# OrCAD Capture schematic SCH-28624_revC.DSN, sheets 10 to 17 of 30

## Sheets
10 08 EC&SD: size B
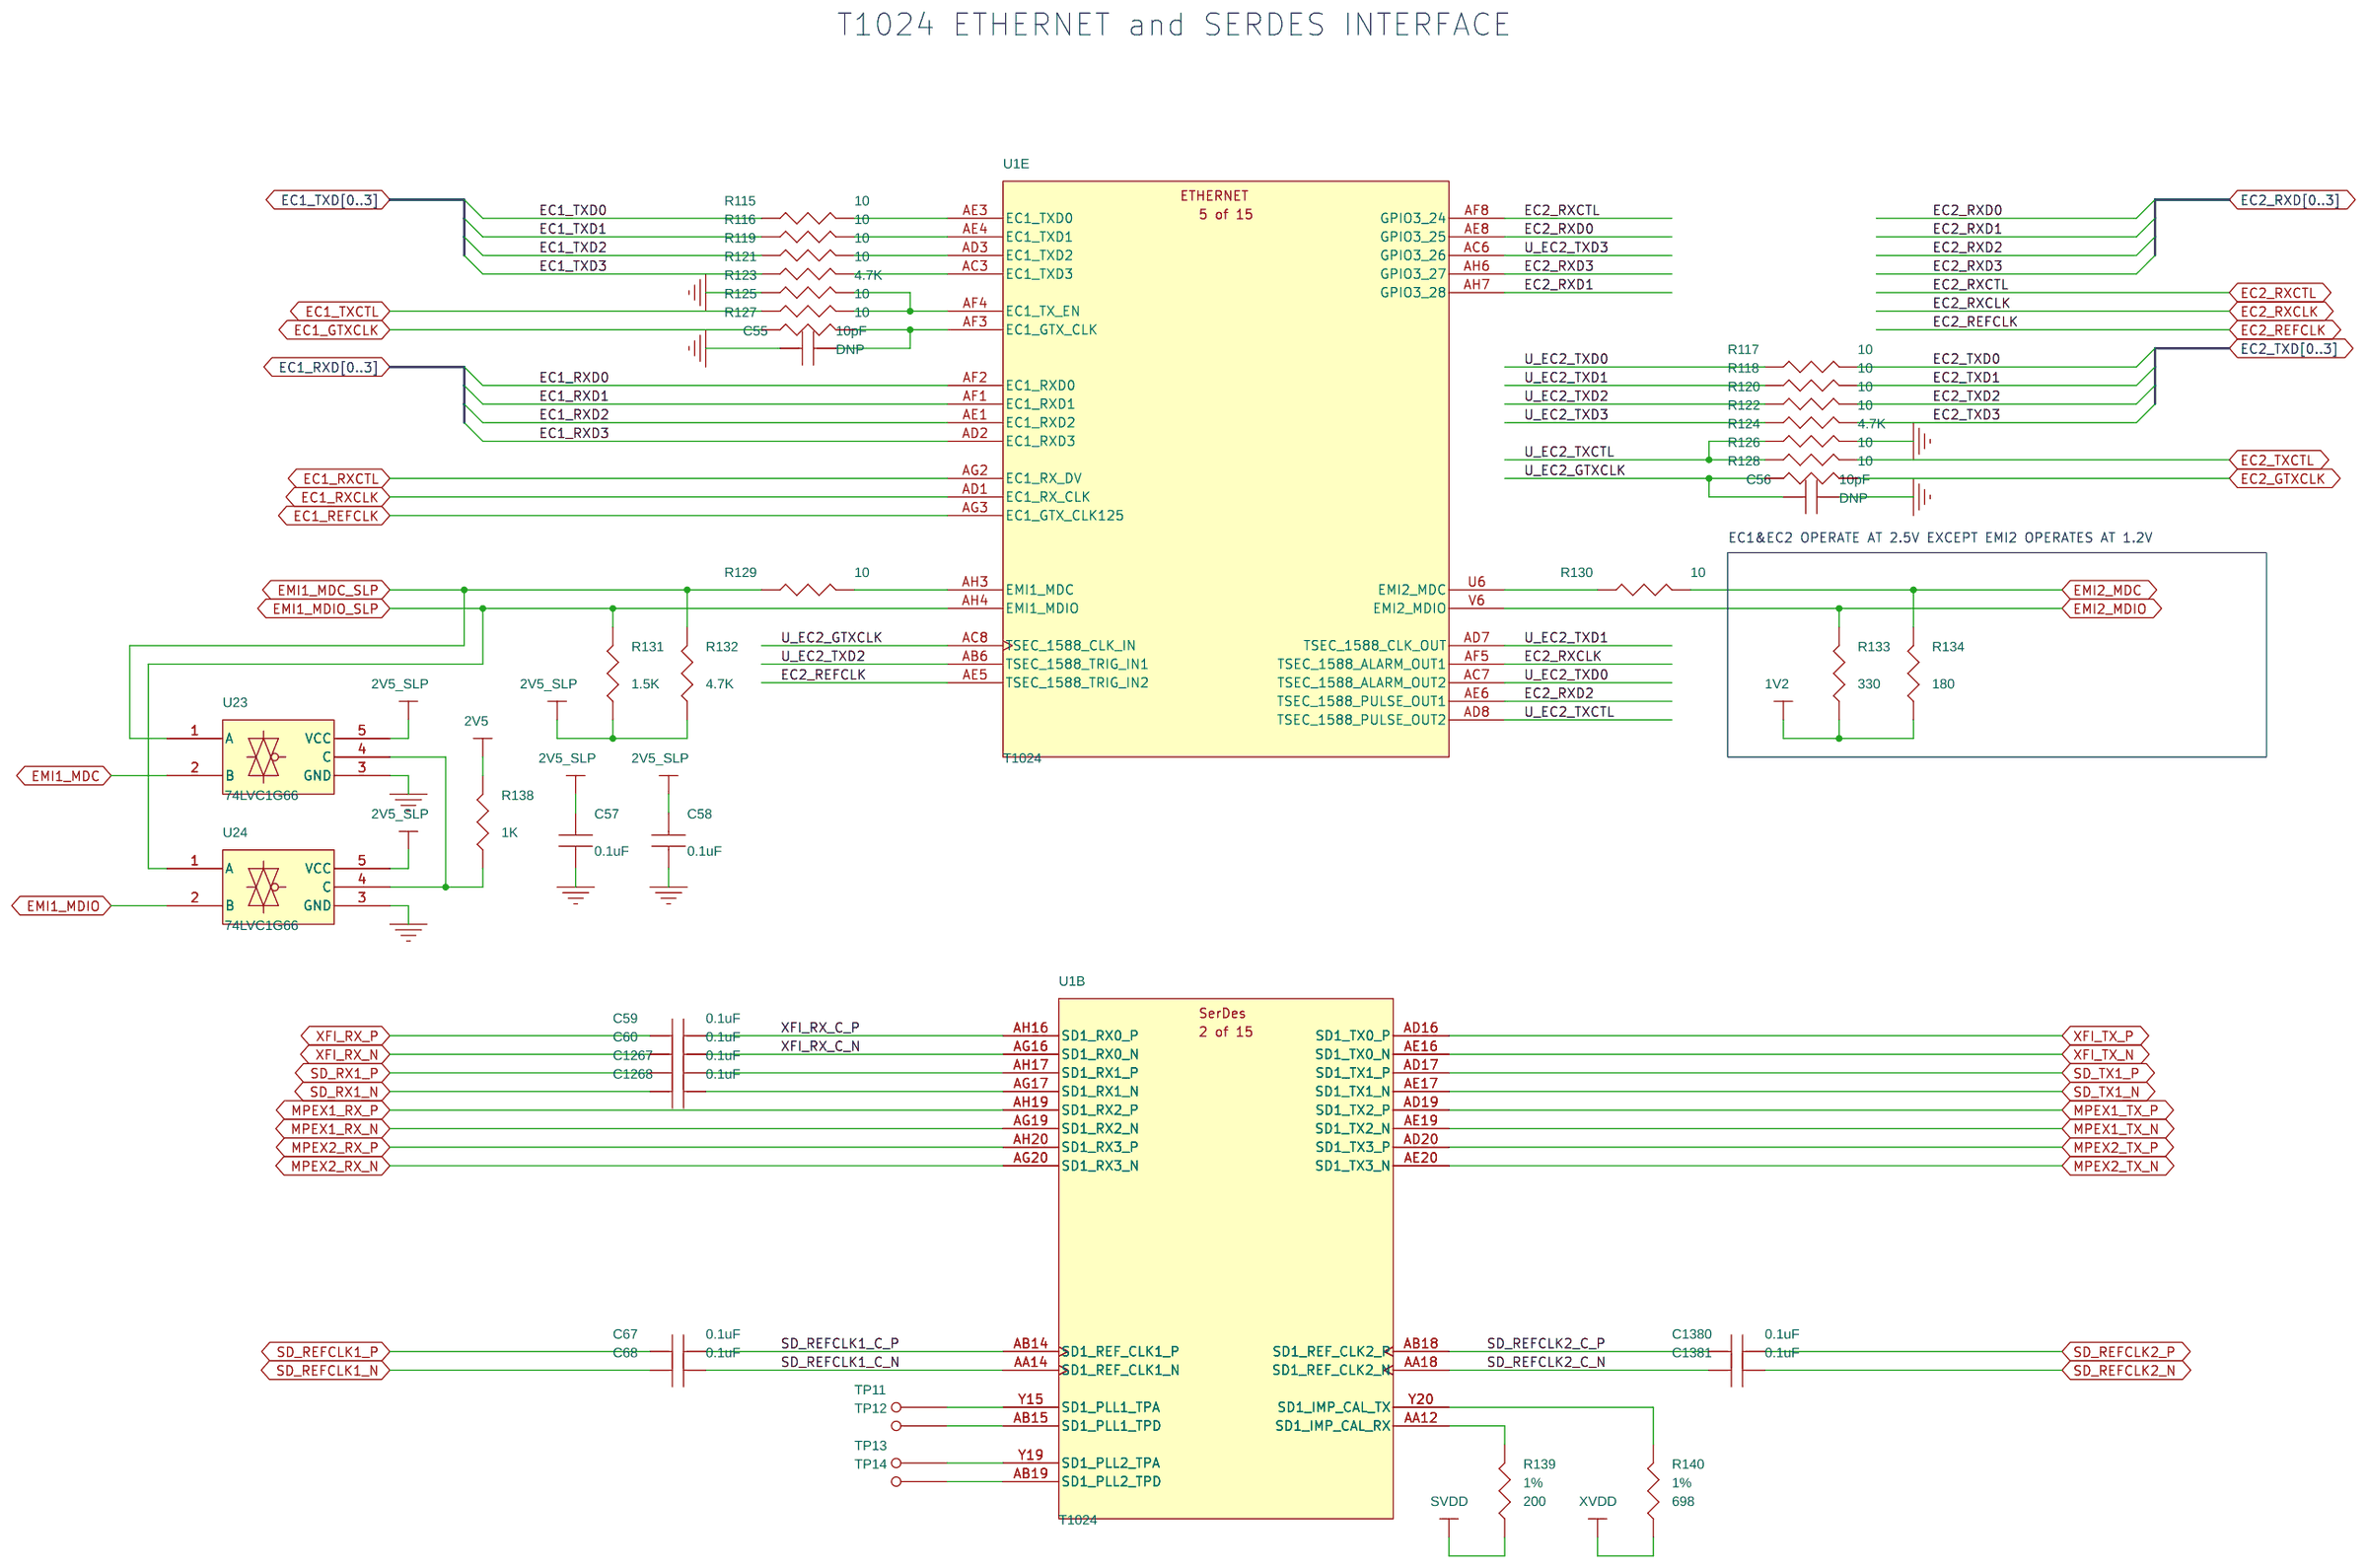
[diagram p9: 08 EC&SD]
11 09 QE: size B
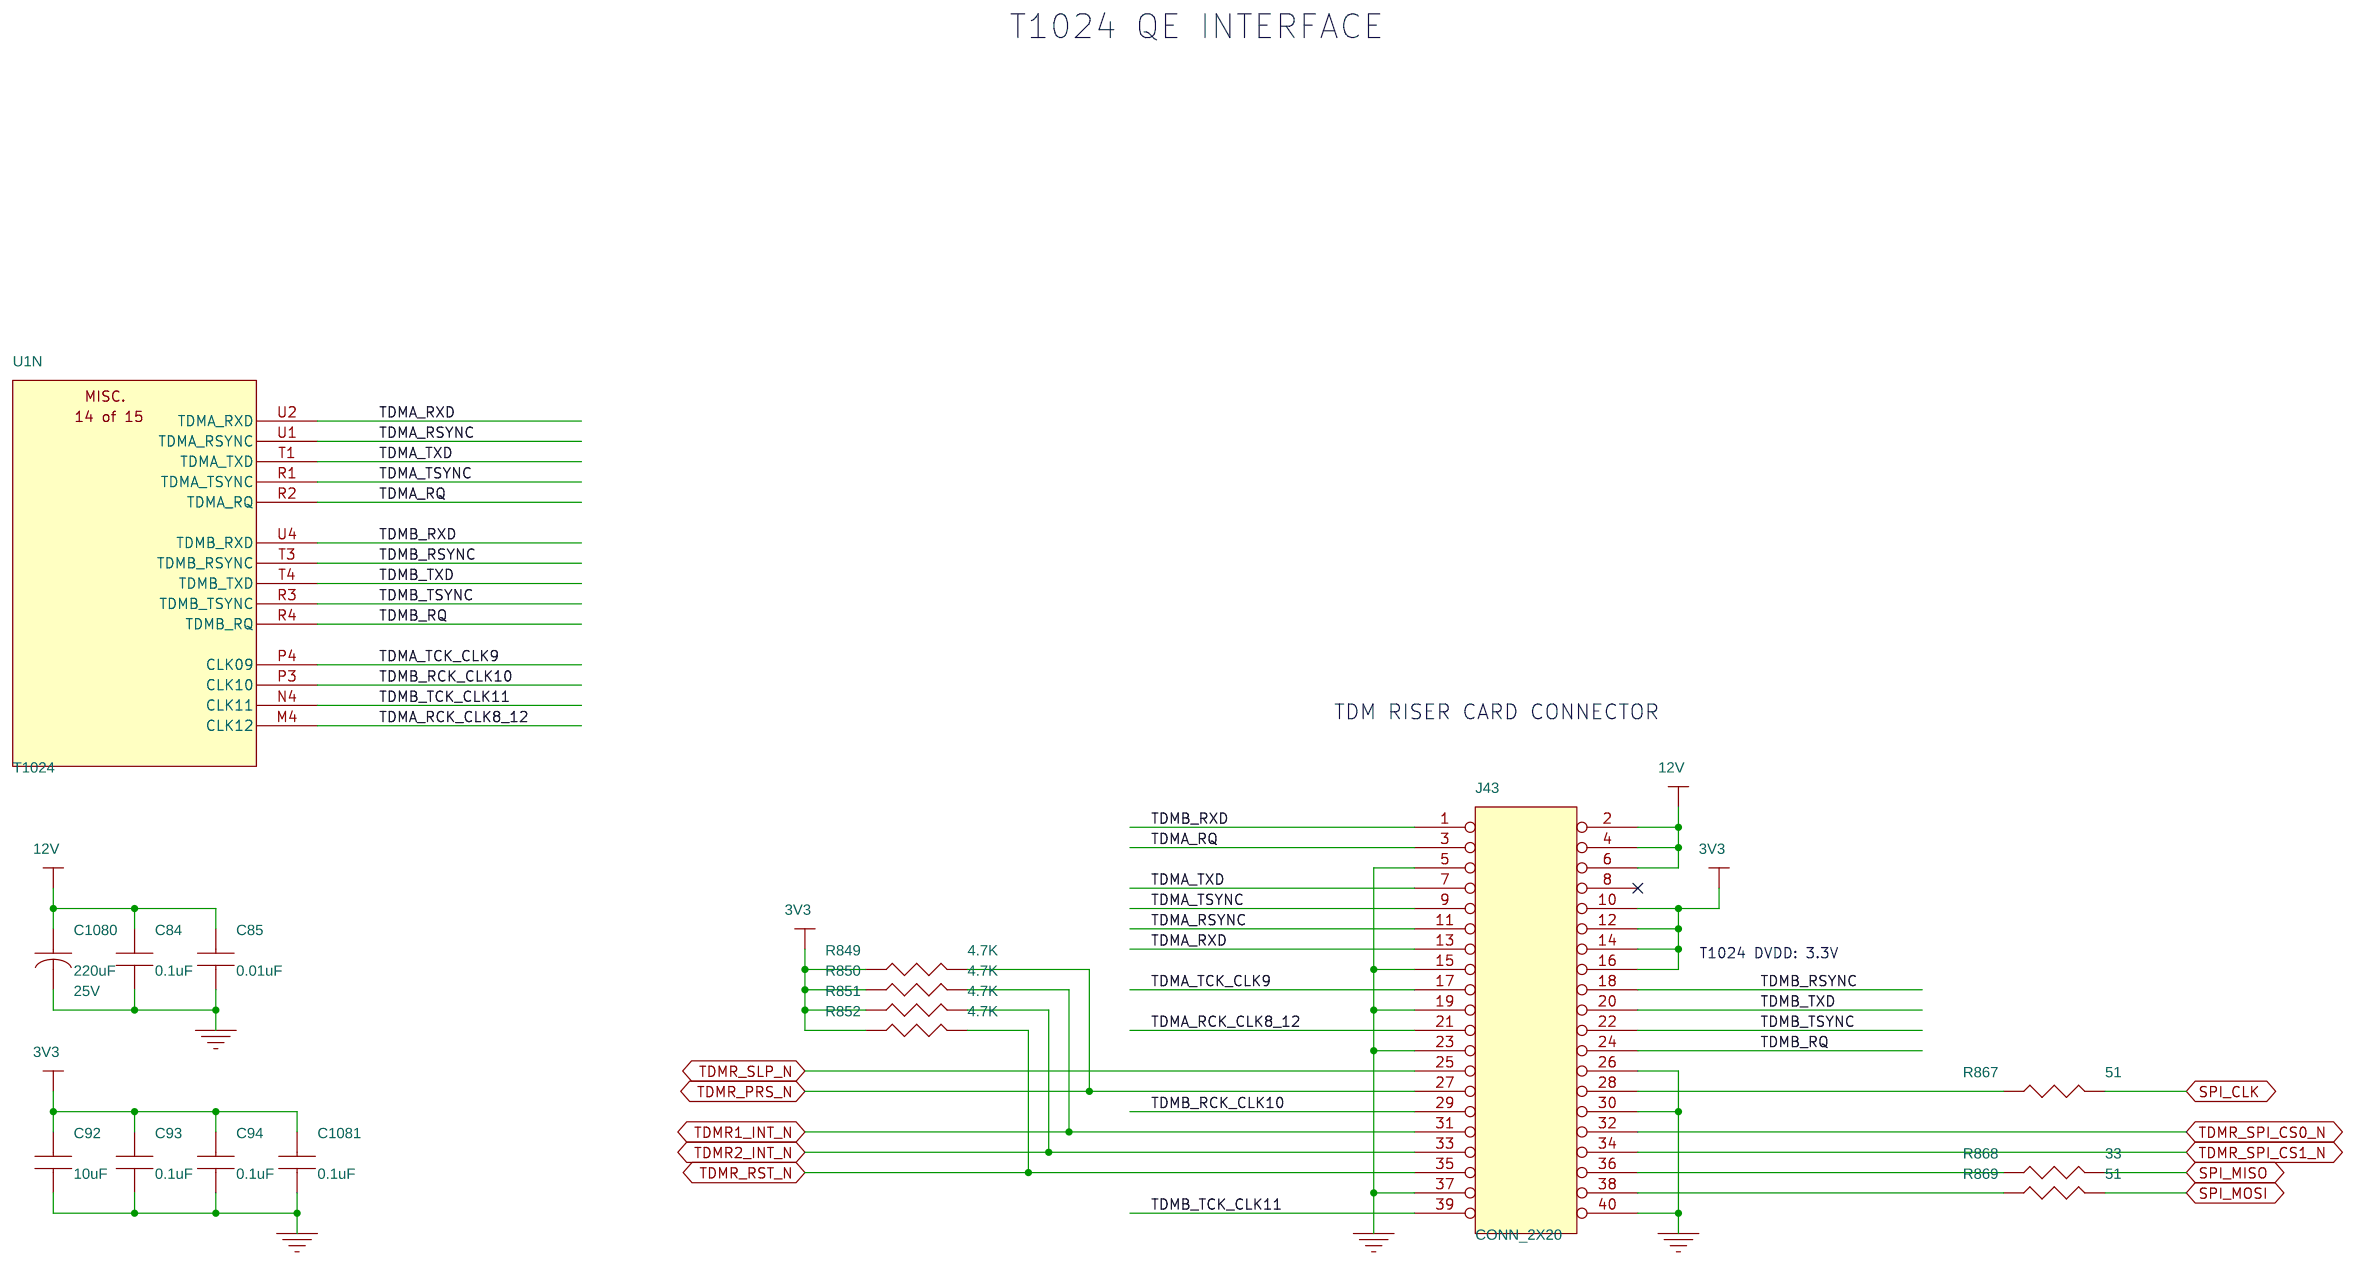
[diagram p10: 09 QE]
12 10 USB: size B
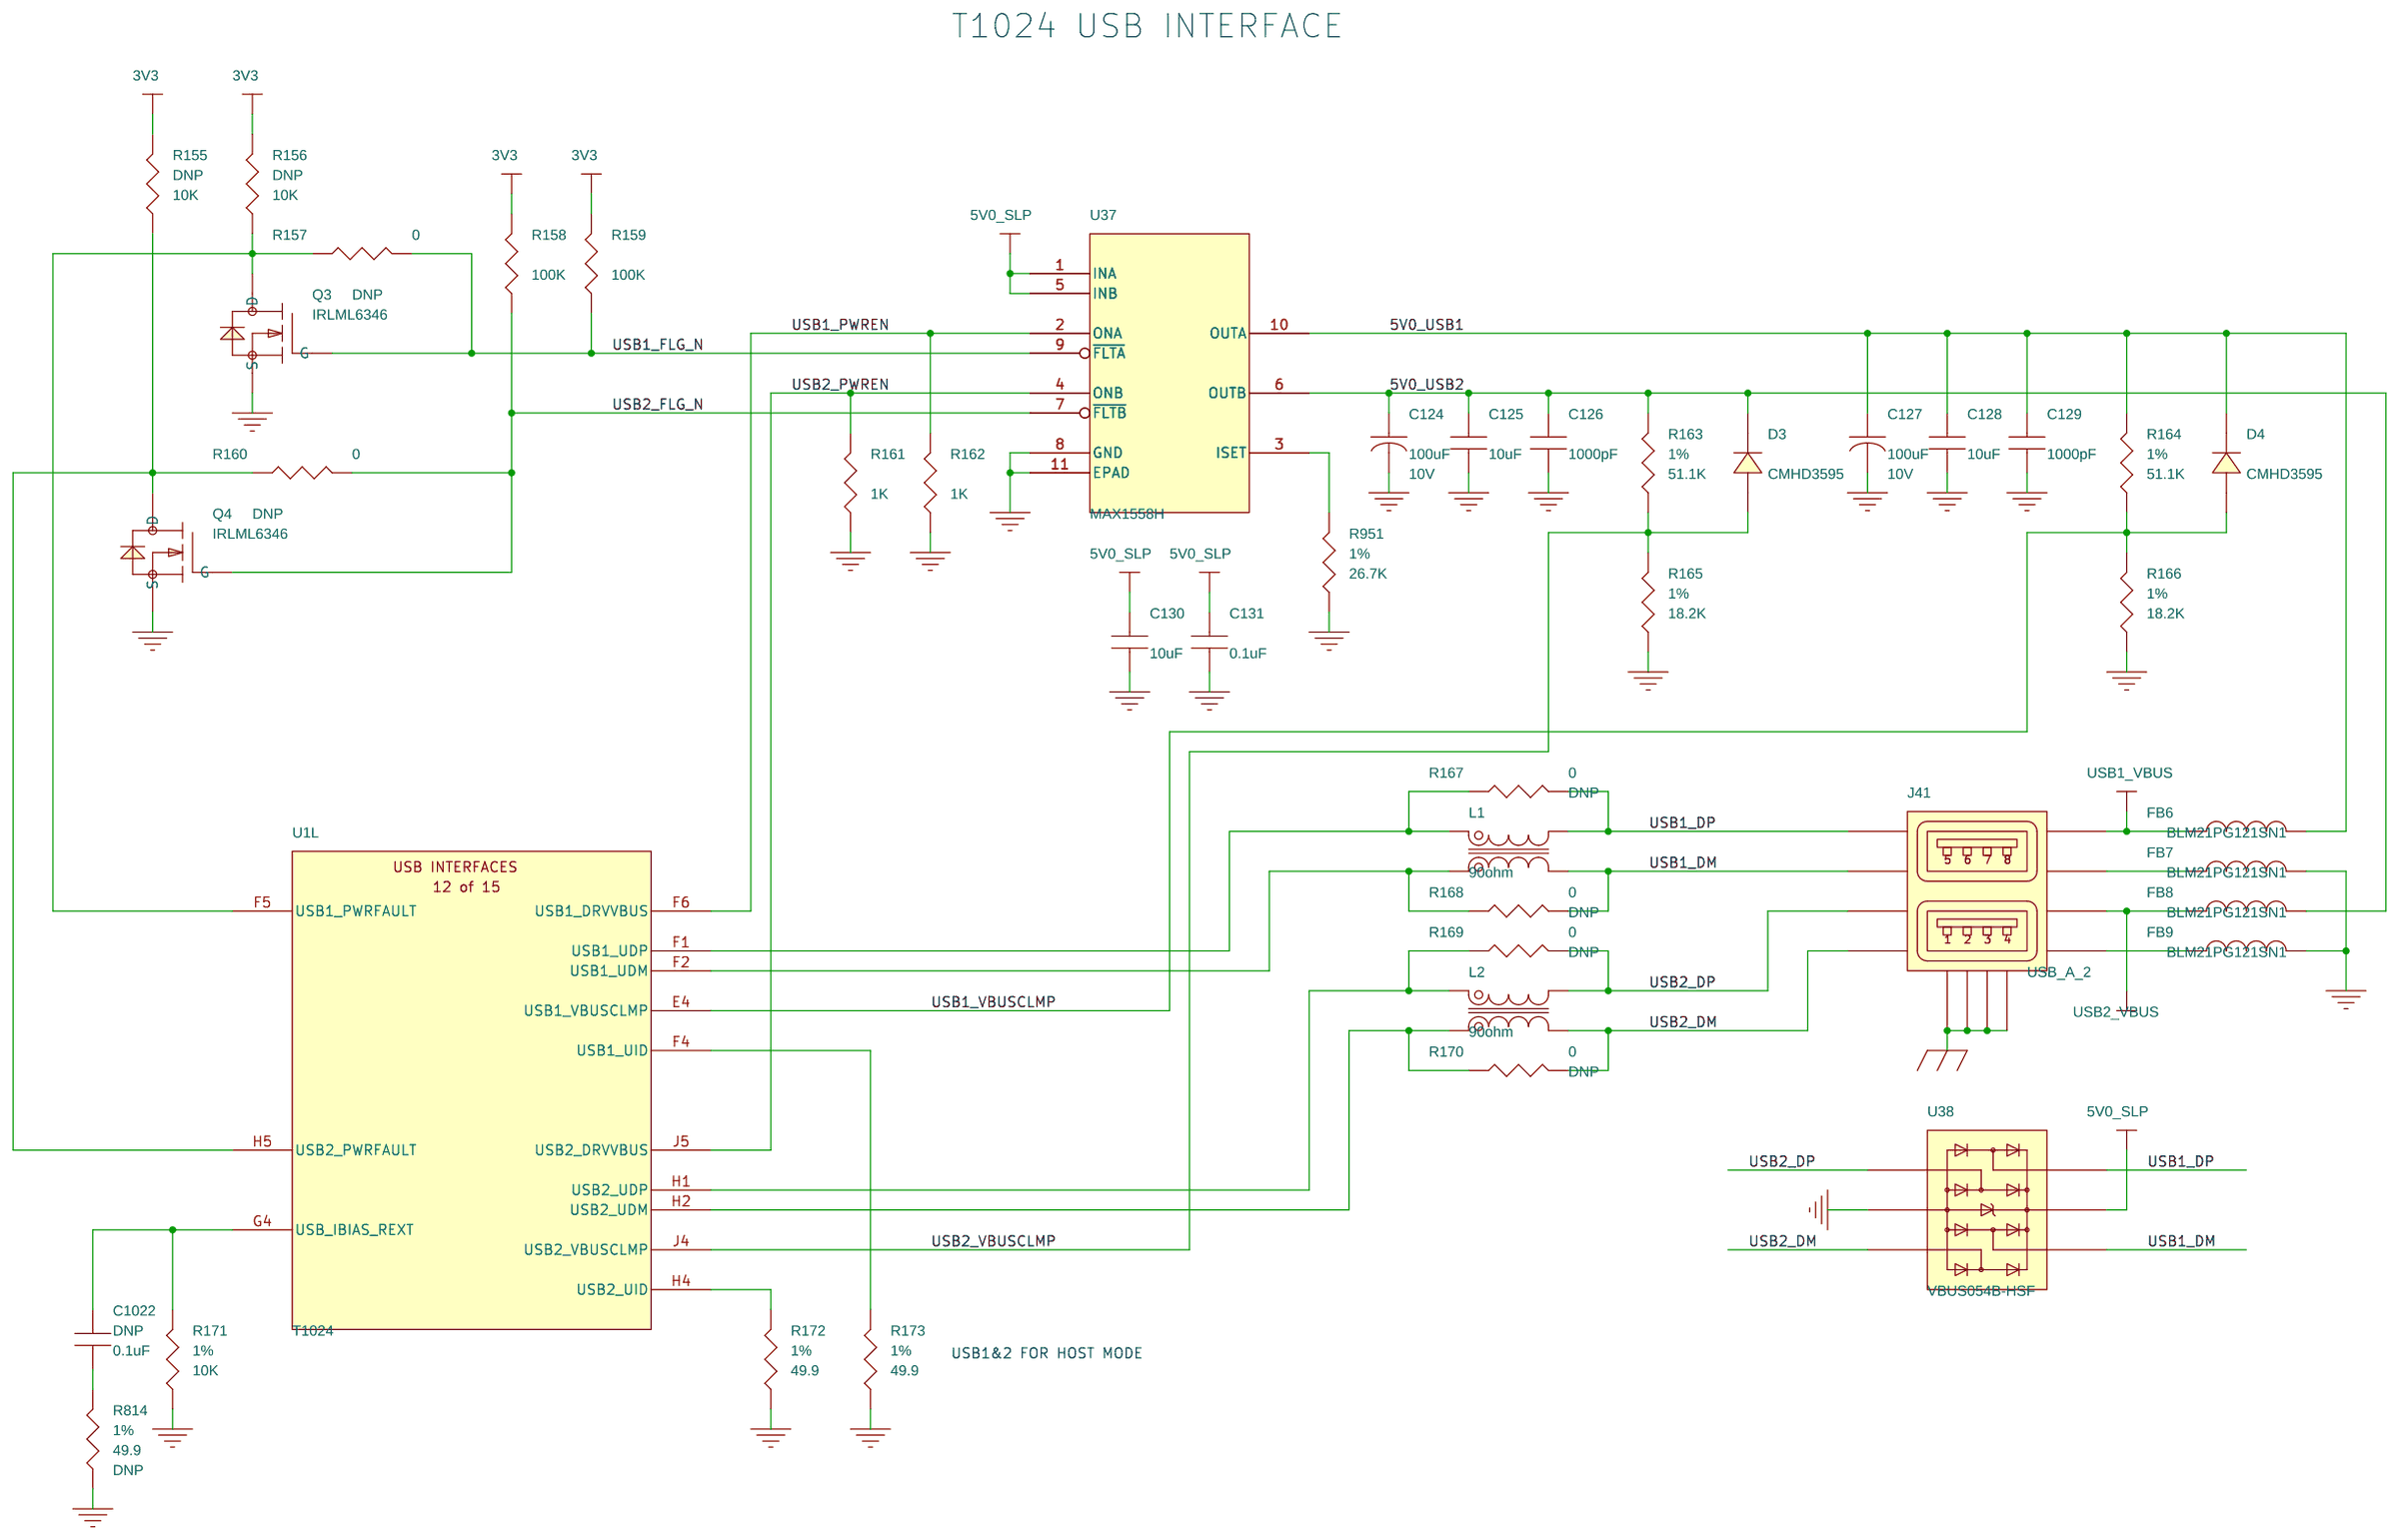
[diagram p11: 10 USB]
13 11 Proc Pwr: size B
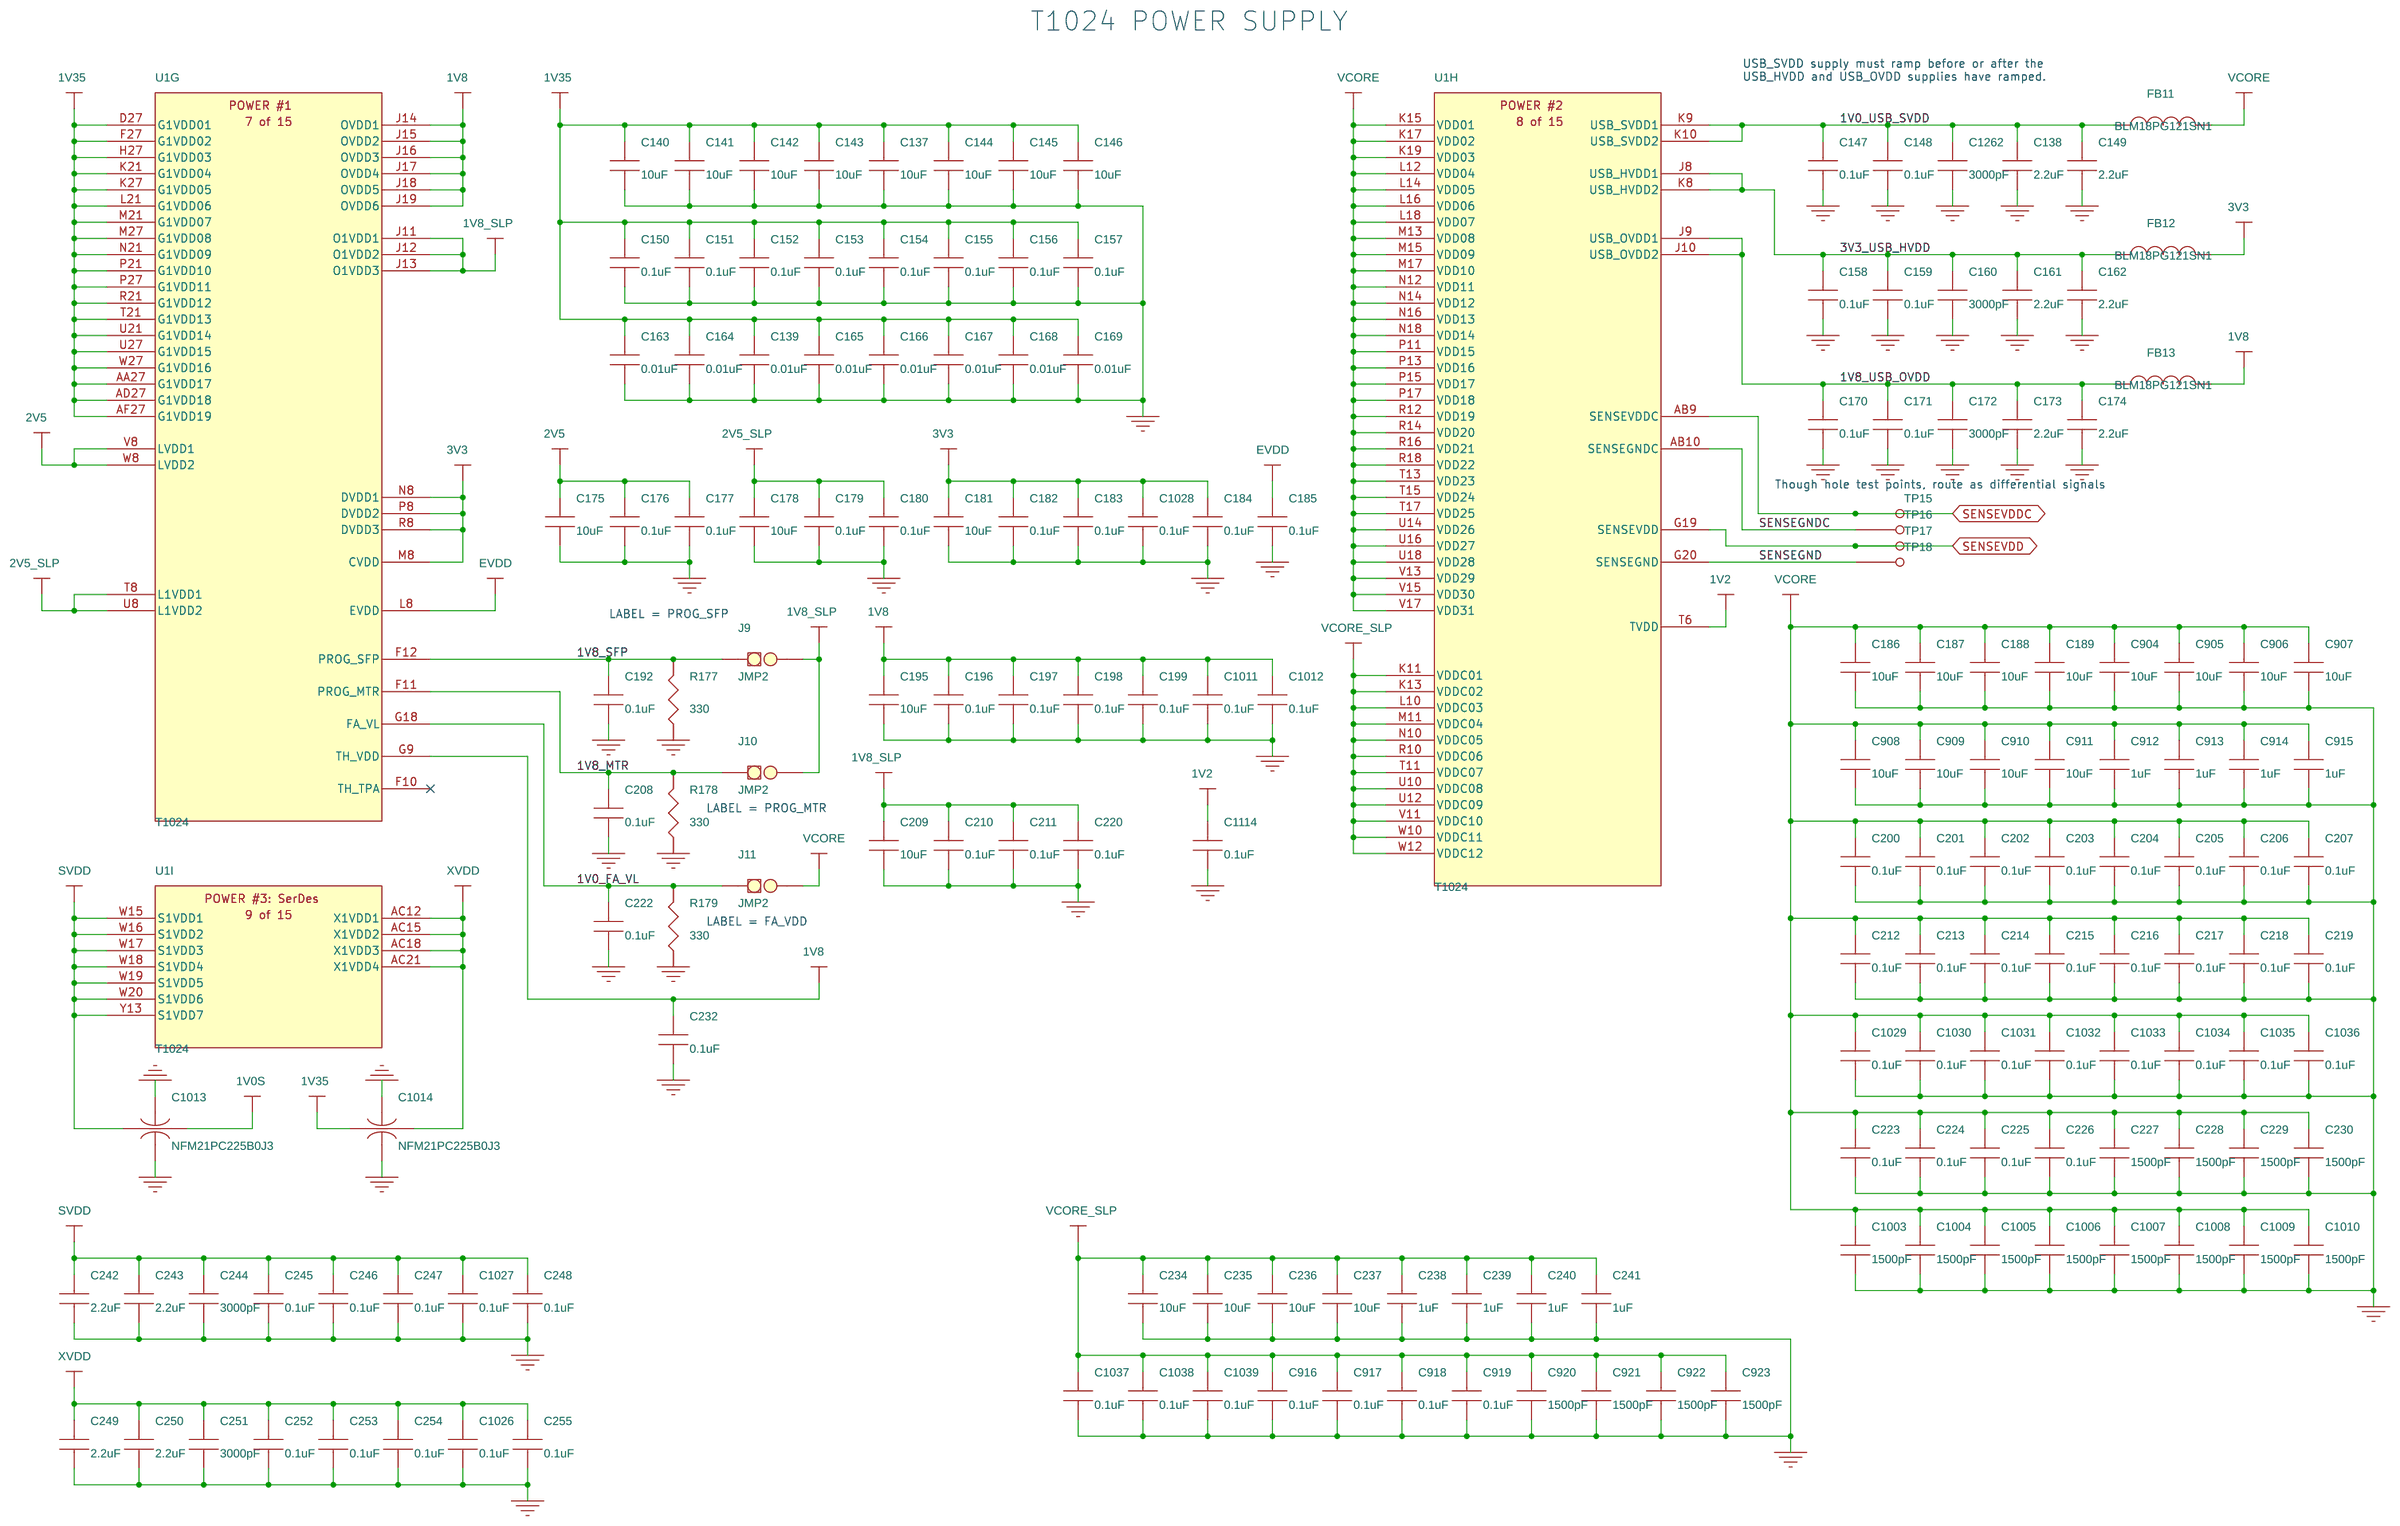
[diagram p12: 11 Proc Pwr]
14 12 Proc Gnd: size B
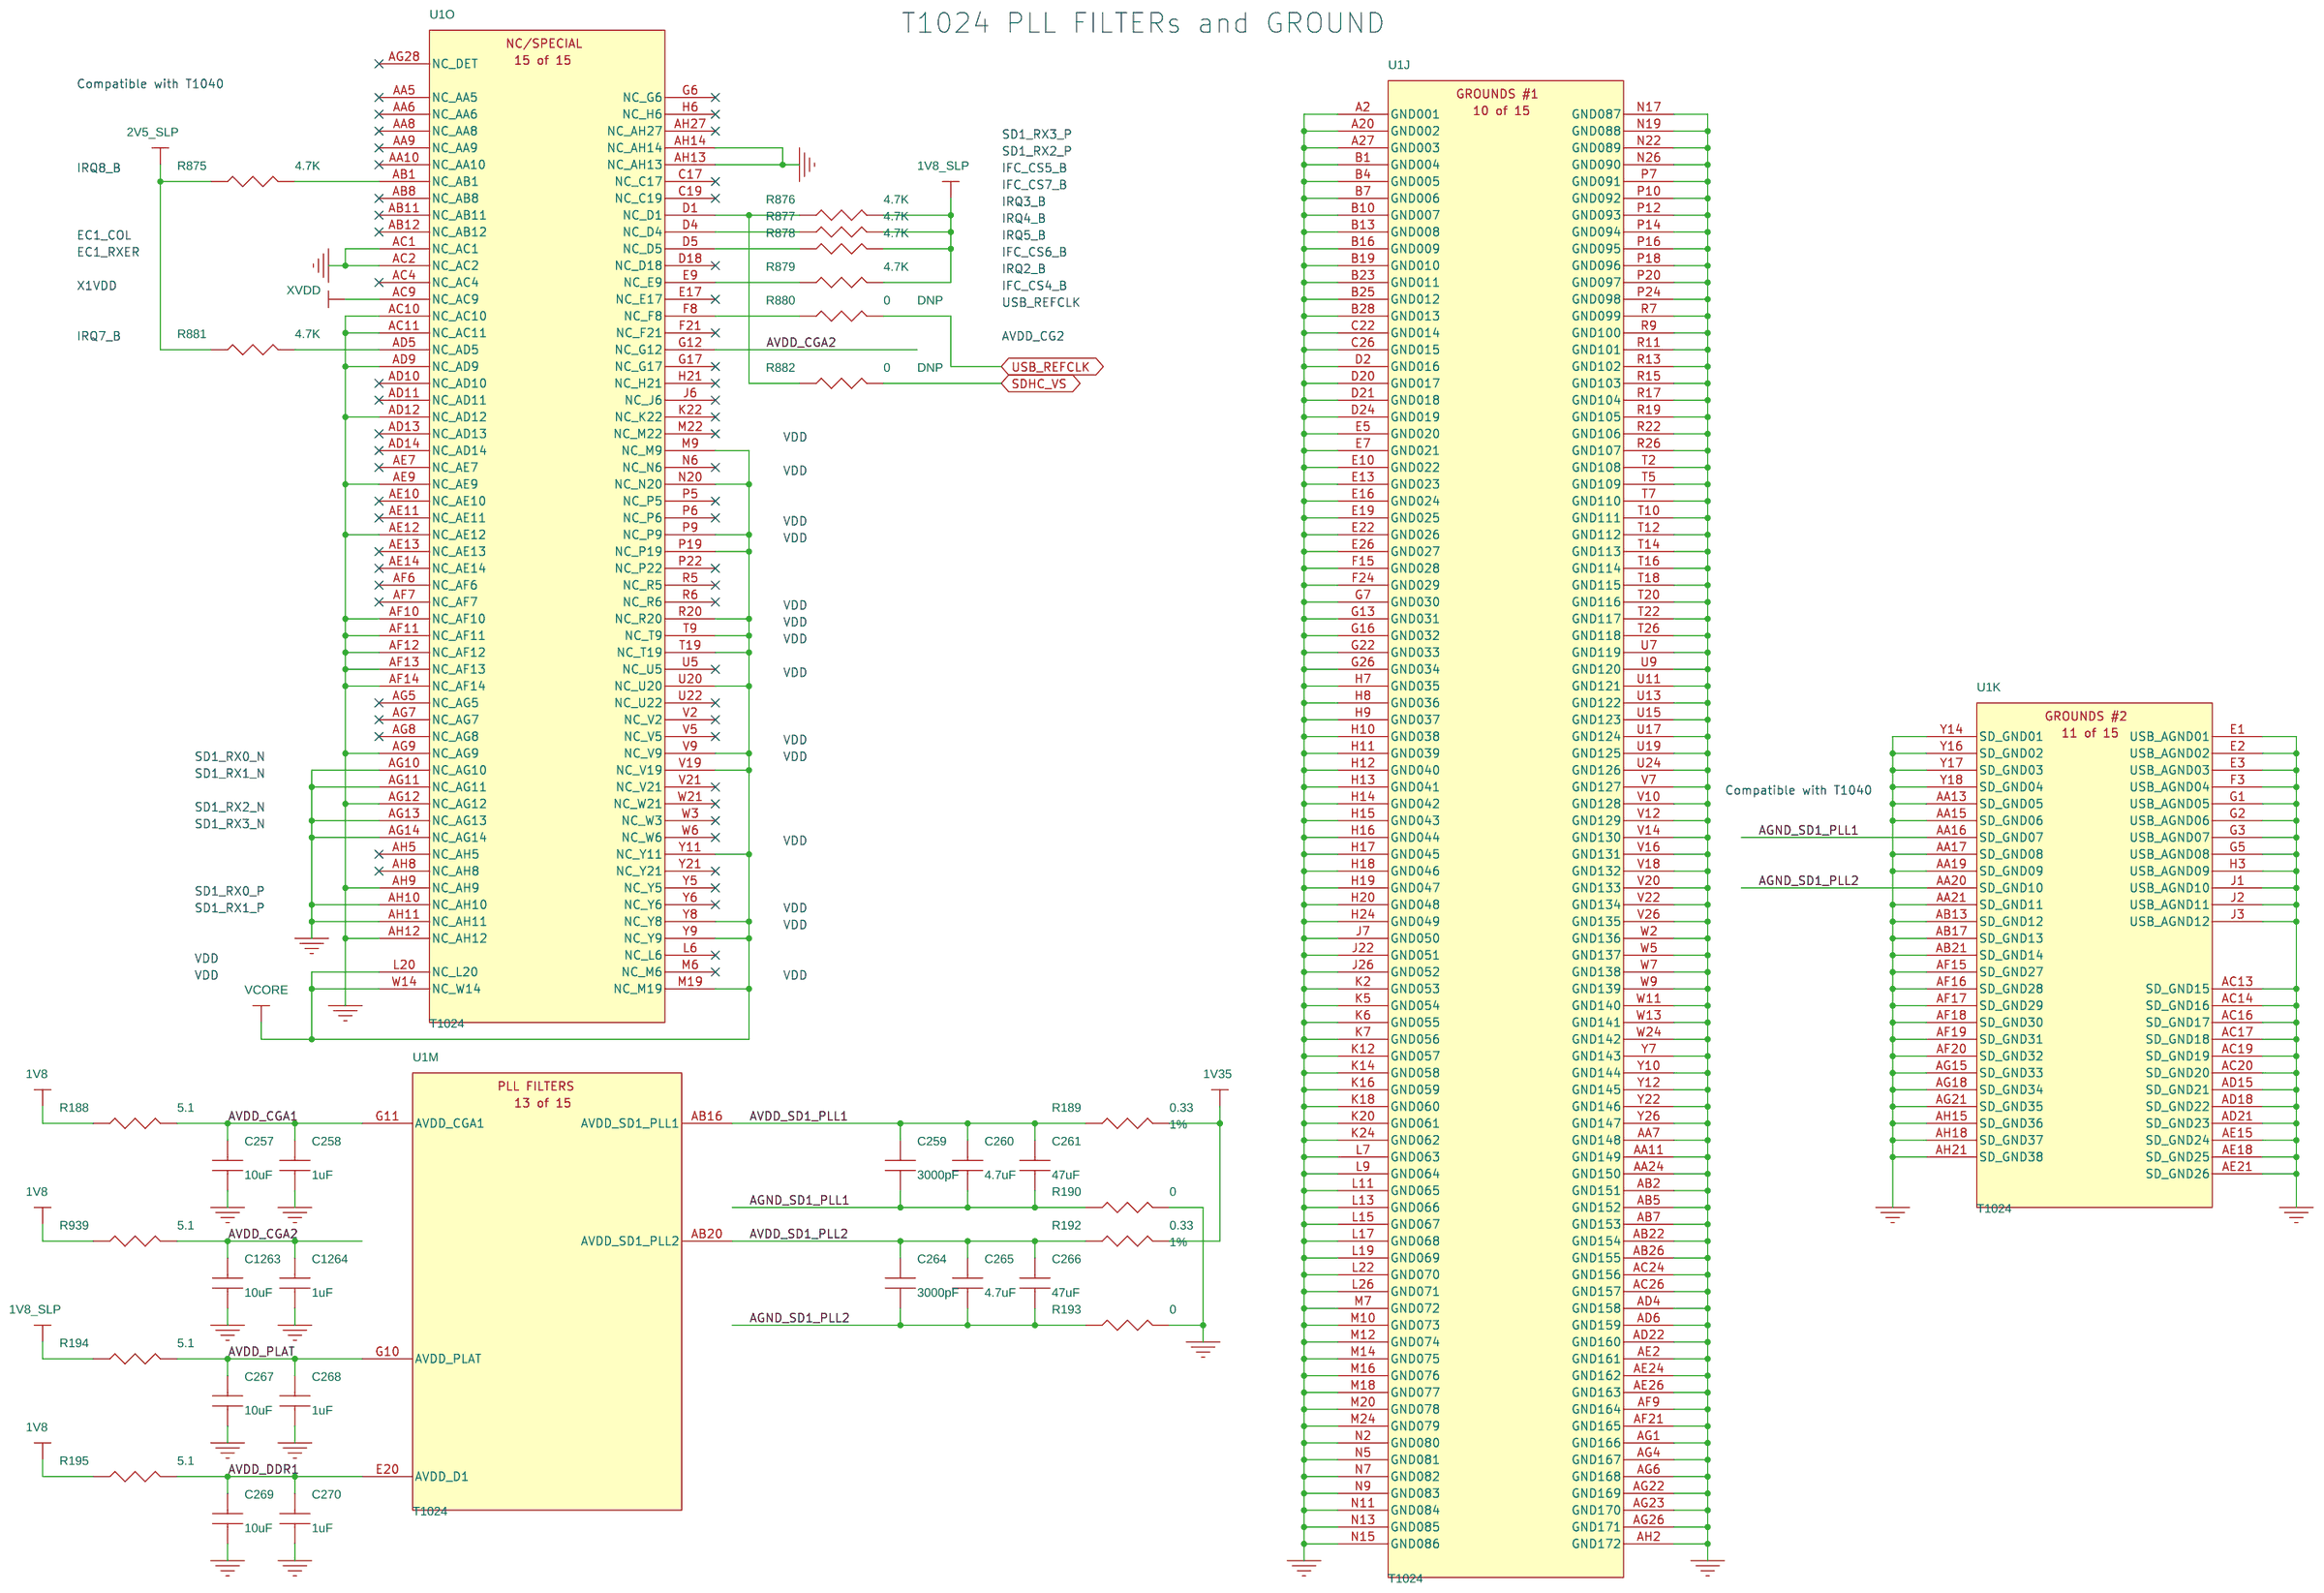
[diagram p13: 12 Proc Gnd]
15 13 UART&I2C: size B
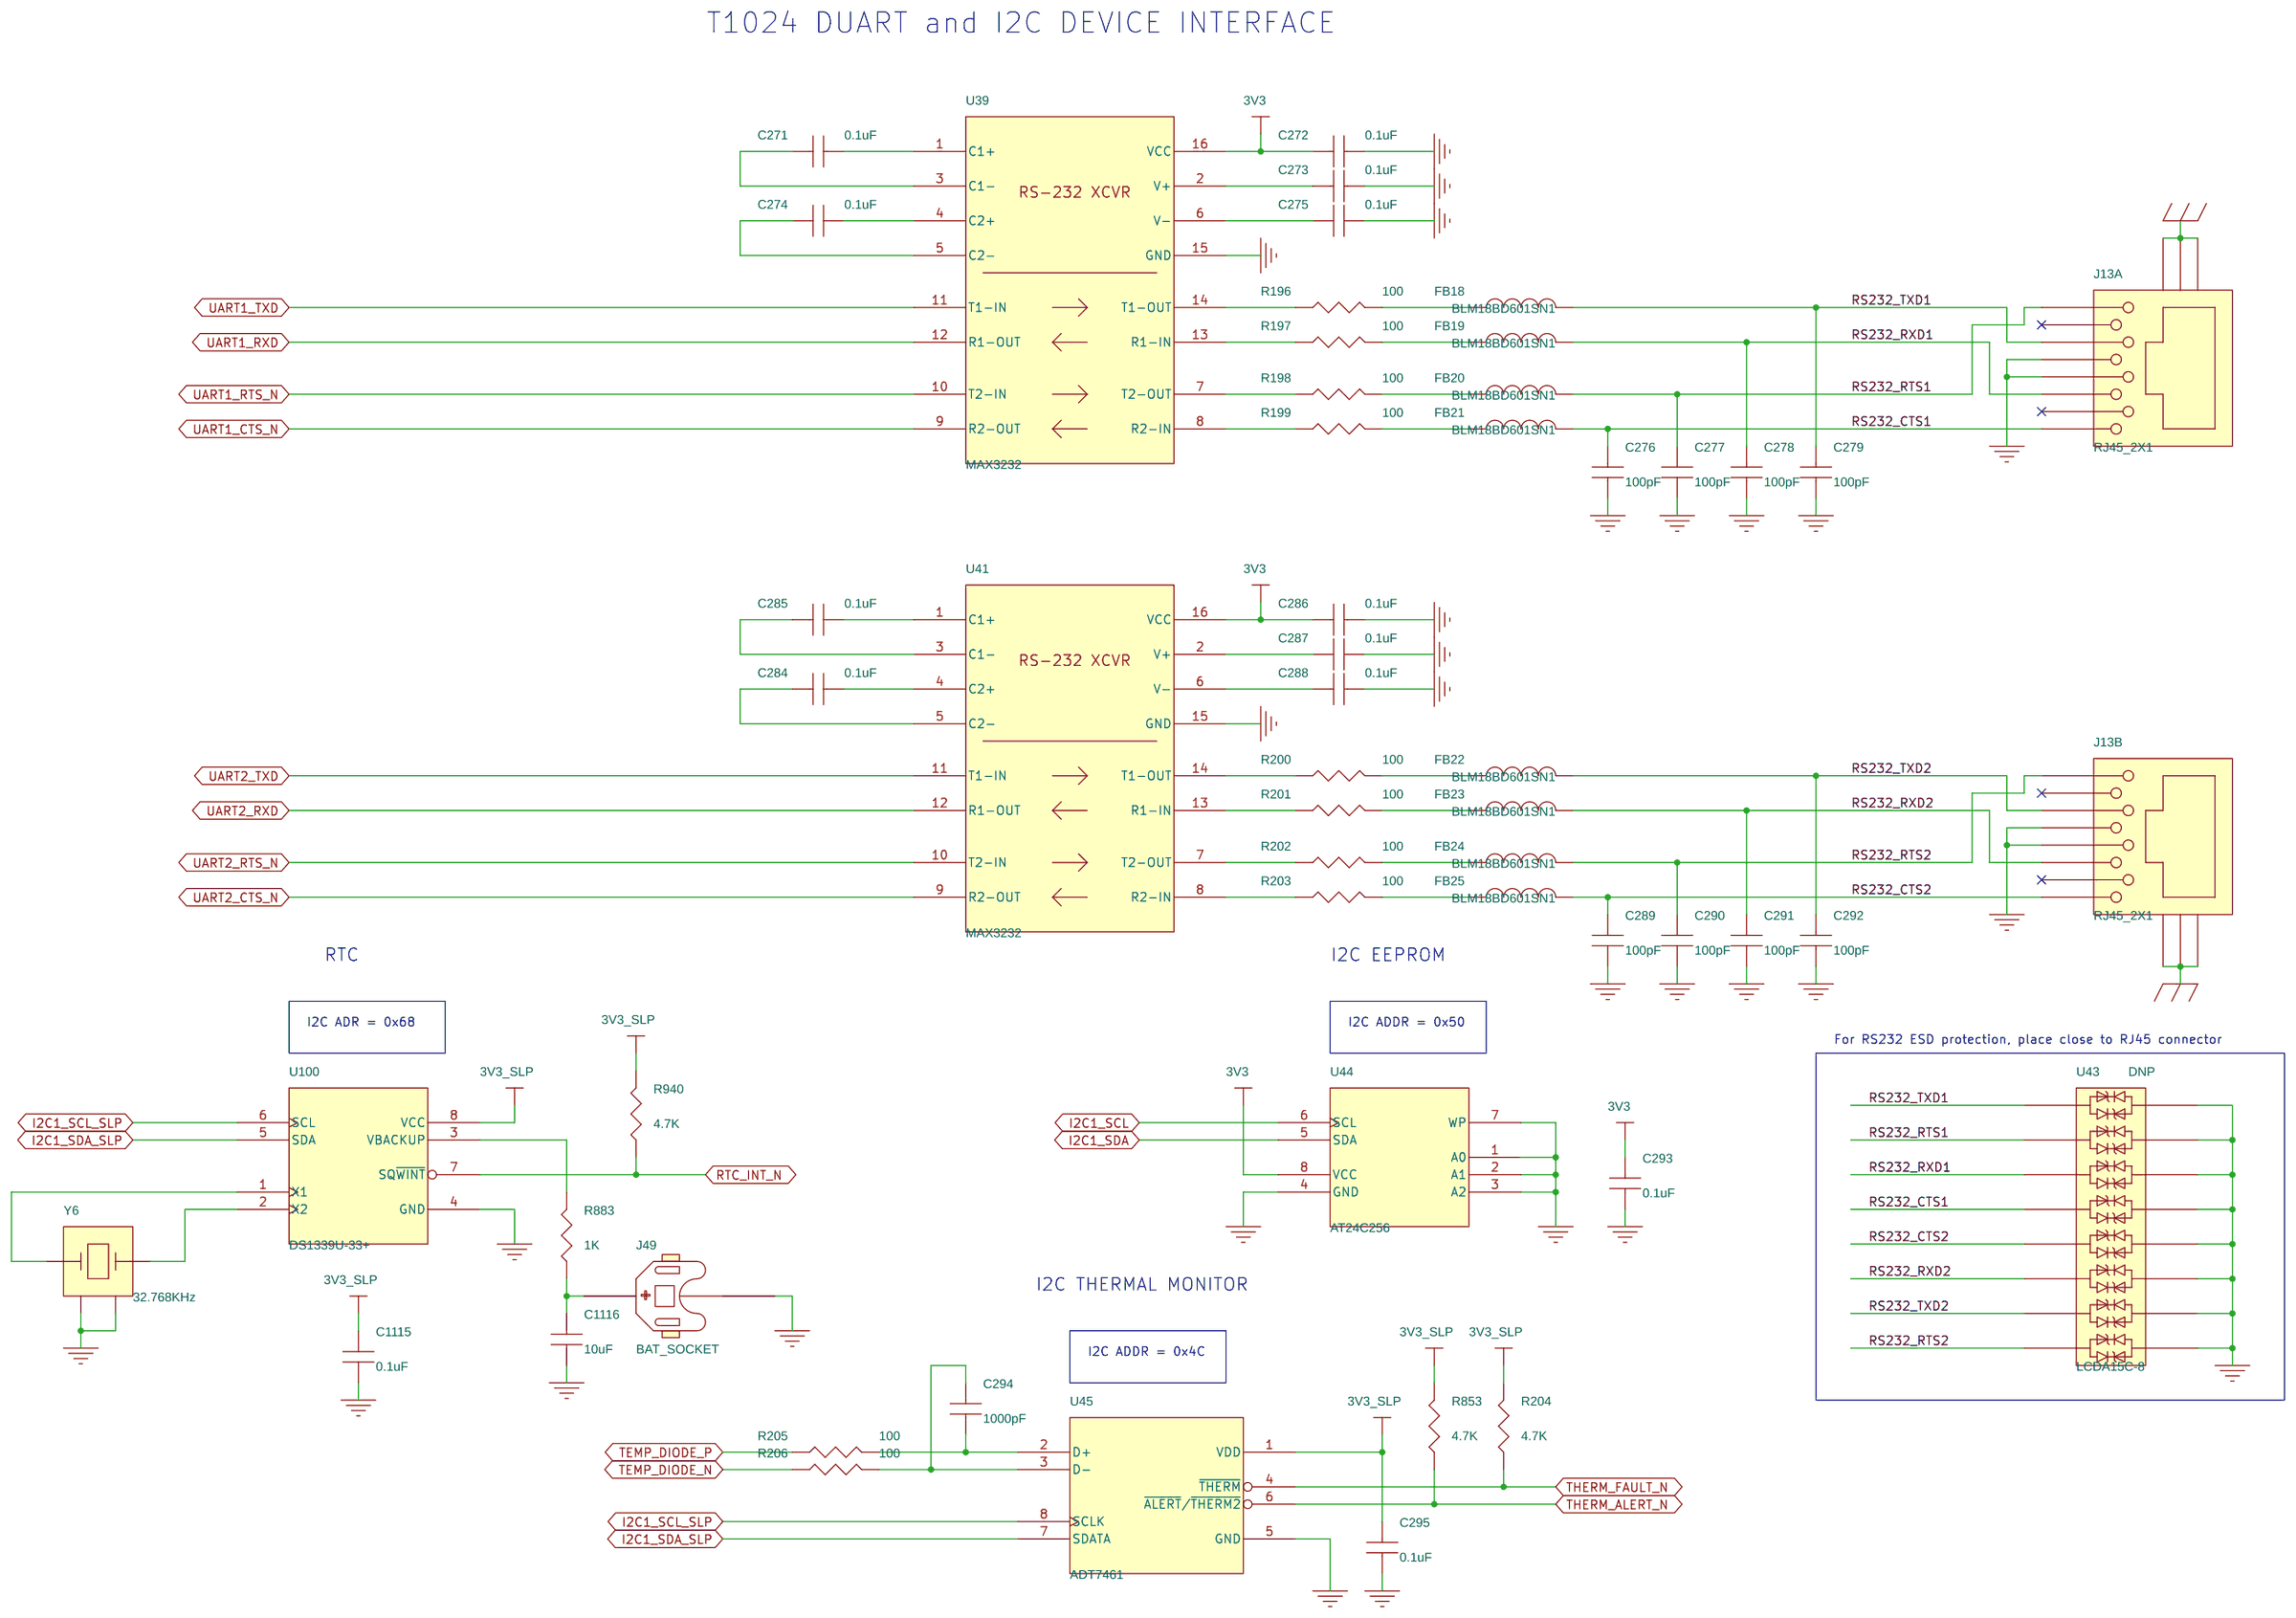
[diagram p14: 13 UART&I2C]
16 14 EC1 PHY: size B
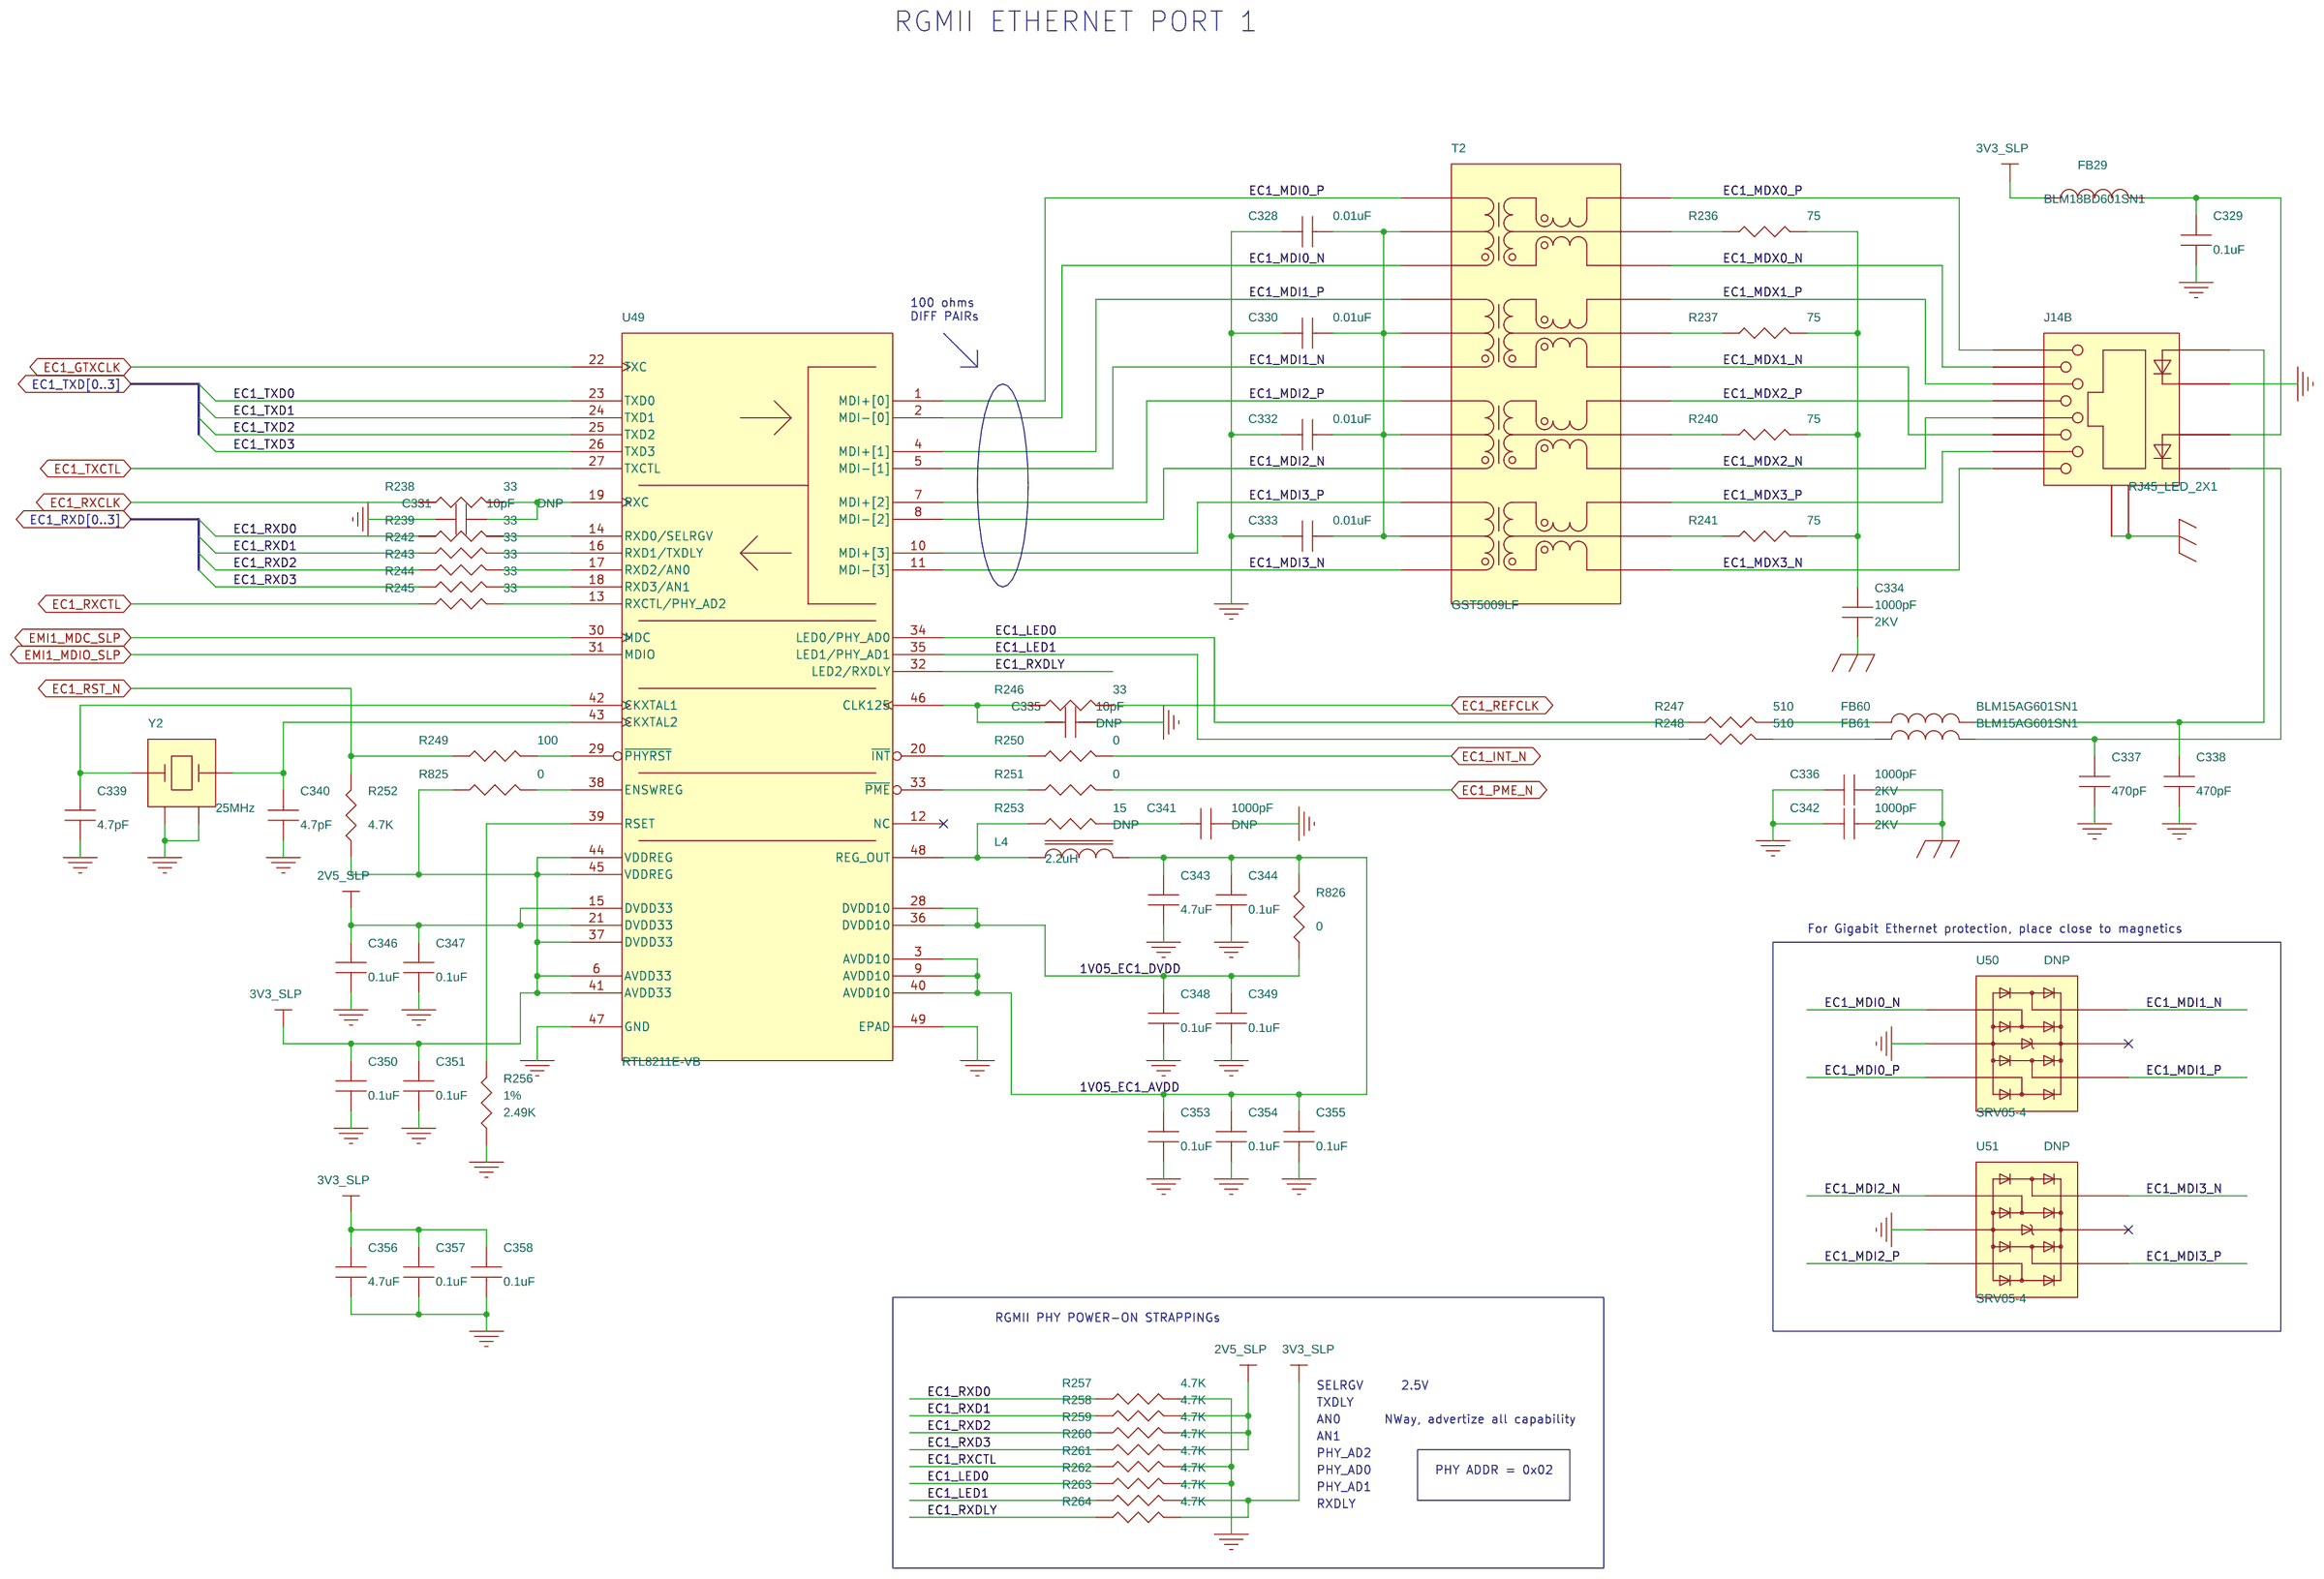
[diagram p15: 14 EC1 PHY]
17 15 EC2 PHY: size B
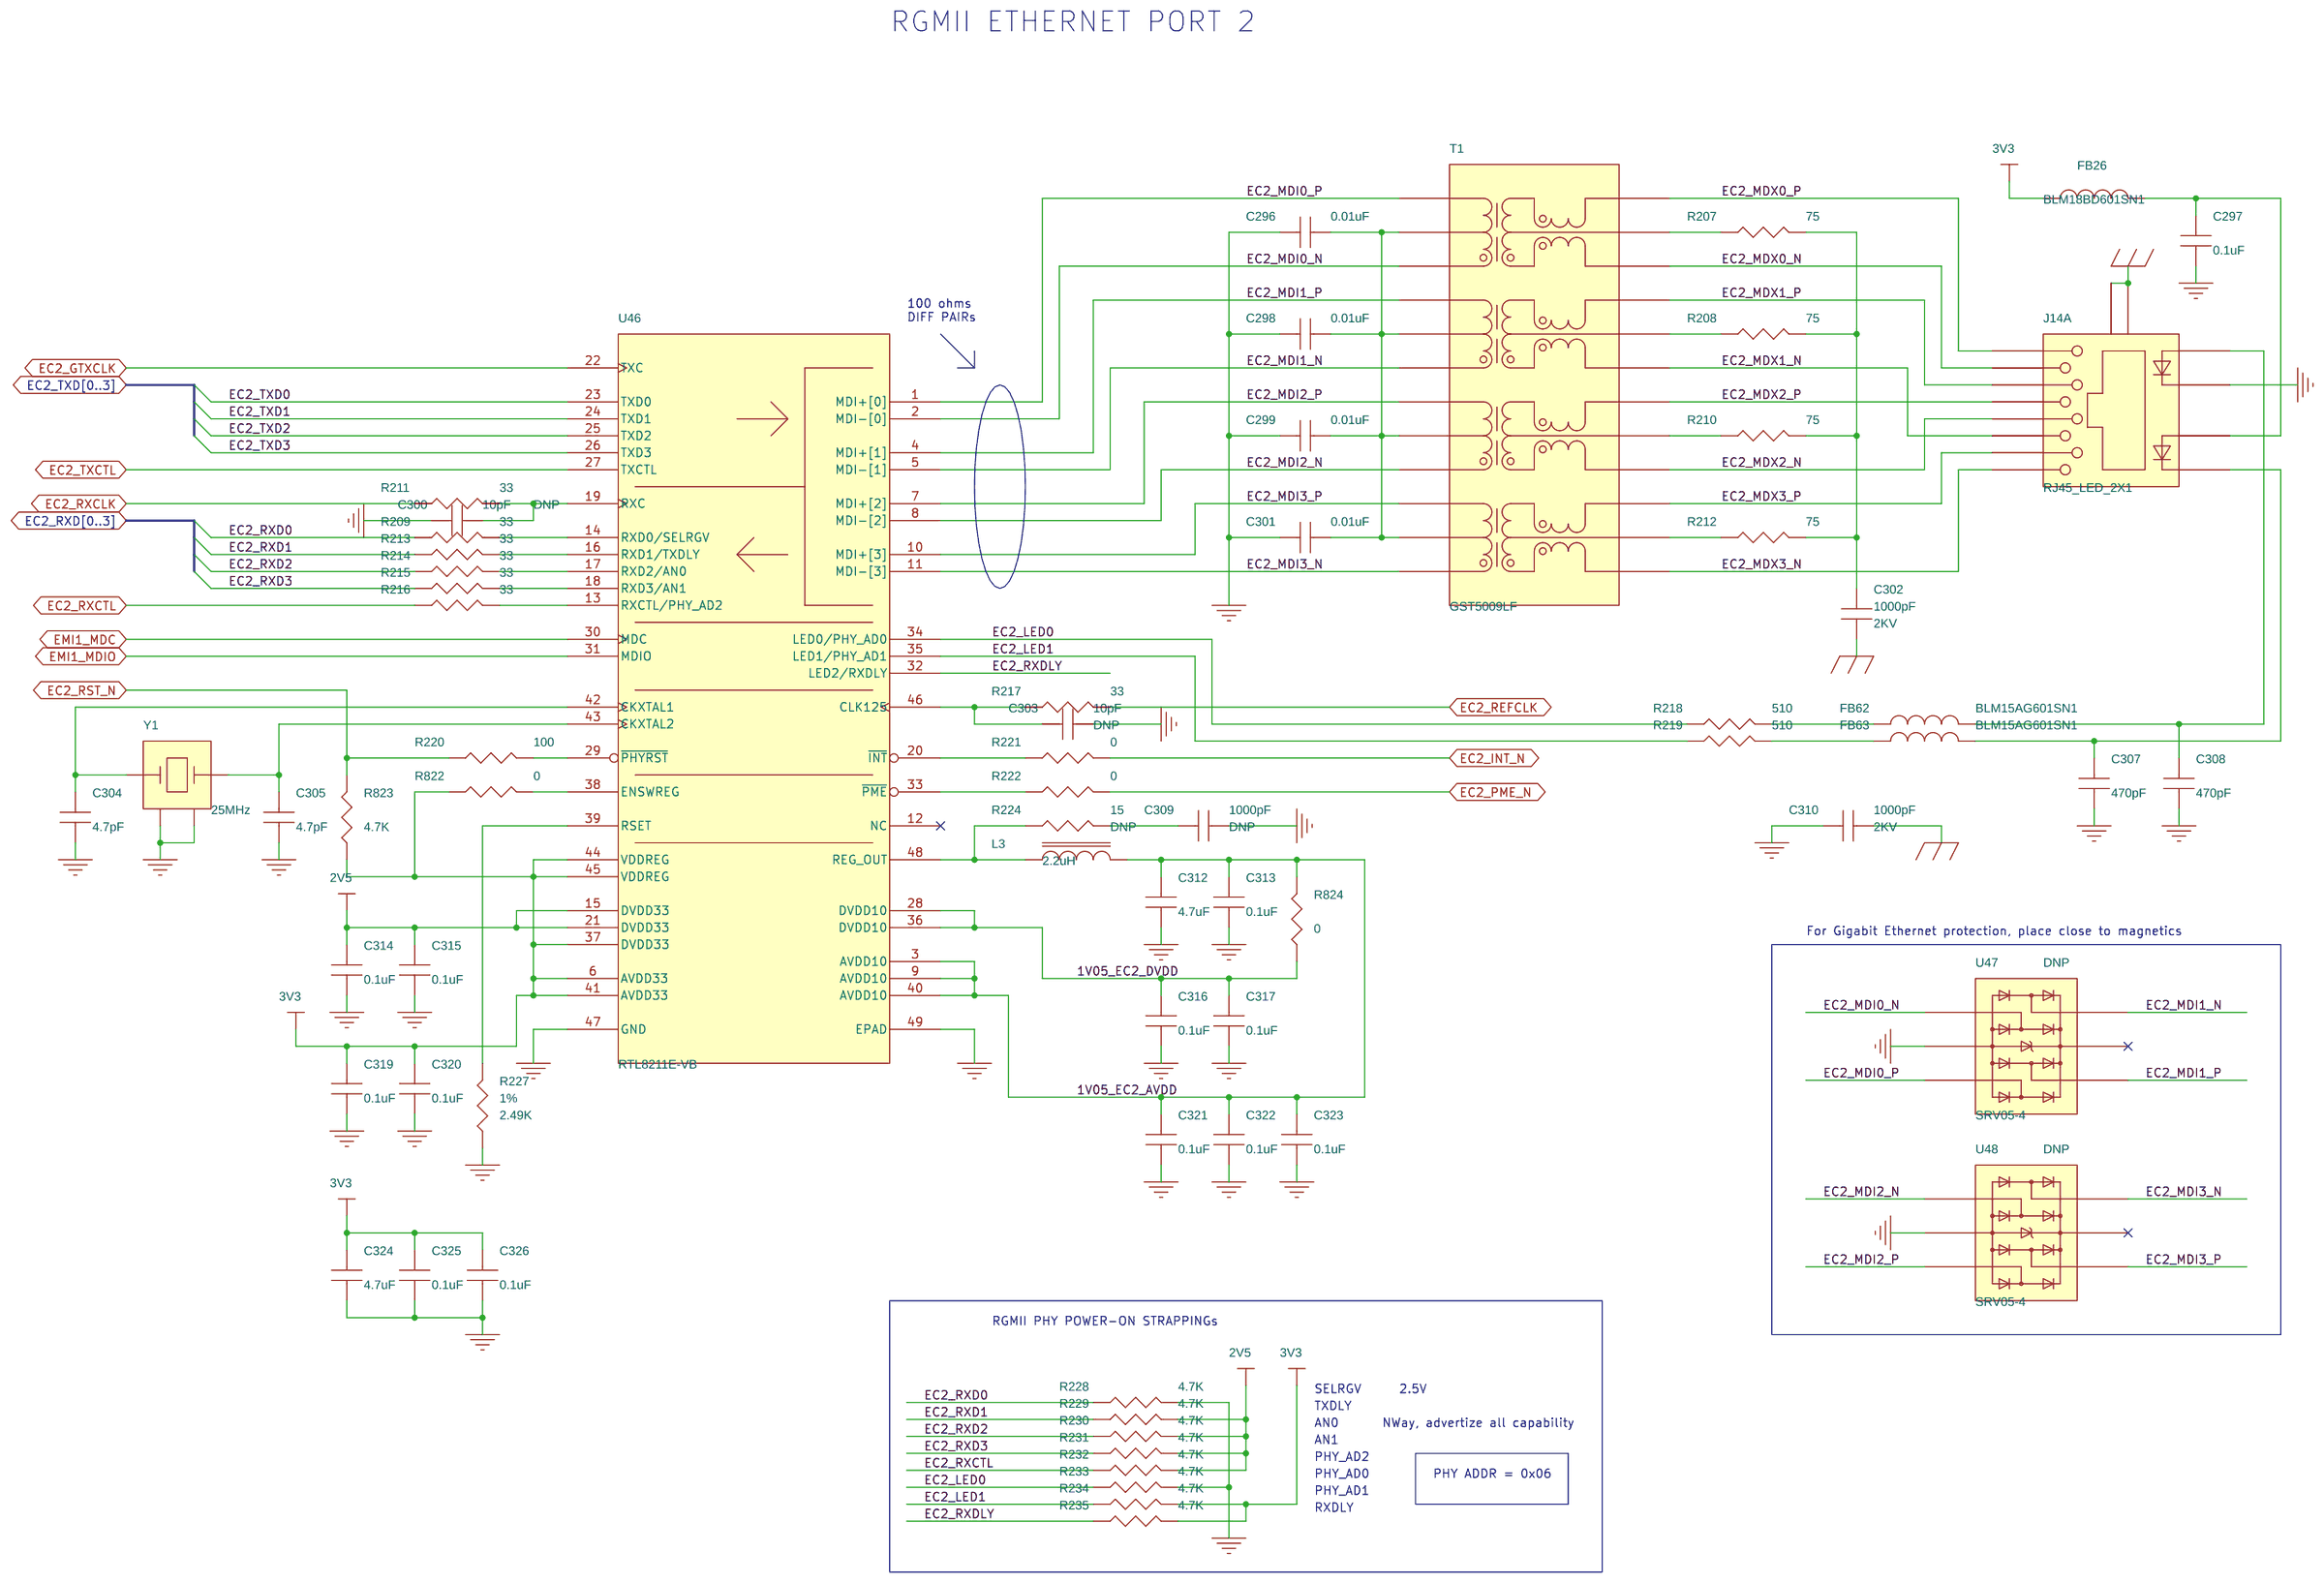
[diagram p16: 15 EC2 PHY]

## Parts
sheet 03 DDR3
U1  T1024  [bga_p080_780]  (sections A,B,C,D,E,F,G,H,I,J,K,L,M,N,O)
sheet 08 EC&SD
C55  10pF  [0402]
C56  10pF  [0402]
C57  0.1uF  [0402]
C58  0.1uF  [0402]
C59  0.1uF  [0402]
C60  0.1uF  [0402]
C67  0.1uF  [0402]
C68  0.1uF  [0402]
C1267  0.1uF  [0402]
C1268  0.1uF  [0402]
C1380  0.1uF  [0402]
C1381  0.1uF  [0402]
R115  10  [0402]
R116  10  [0402]
R117  10  [0402]
R118  10  [0402]
R119  10  [0402]
R120  10  [0402]
R121  10  [0402]
R122  10  [0402]
R123  4.7K  [0402]
R124  4.7K  [0402]
R125  10  [0402]
R126  10  [0402]
R127  10  [0402]
R128  10  [0402]
R129  10  [0402]
R130  10  [0402]
R131  1.5K  [0402]
R132  4.7K  [0402]
R133  330  [0402]
R134  180  [0402]
R138  1K  [0402]
R139  200  [0402]
R140  698  [0402]
TP11  TP  [tp]
TP12  TP  [tp]
TP13  TP  [tp]
TP14  TP  [tp]
U23  74LVC1G66  [sc70_5]
U24  74LVC1G66  [sc70_5]
sheet 09 QE
C84  0.1uF  [0603]
C85  0.01uF  [0402]
C92  10uF  [0603]
C93  0.1uF  [0402]
C94  0.1uF  [0402]
C1080  220uF  [cape_b8]
C1081  0.1uF  [0402]
J43  CONN_2X20  [con_mec6_120]
R849  4.7K  [0402]
R850  4.7K  [0402]
R851  4.7K  [0402]
R852  4.7K  [0402]
R867  51  [0402]
R868  33  [0402]
R869  51  [0402]
sheet 10 USB
C124  100uF  [7343]
C125  10uF  [0805]
C126  1000pF  [0402]
C127  100uF  [7343]
C128  10uF  [0805]
C129  1000pF  [0402]
C130  10uF  [0805]
C131  0.1uF  [0402]
C1022  0.1uF  [0402]
D3  CMHD3595  [sod123]
D4  CMHD3595  [sod123]
FB6  BLM21PG121SN1  [0805]
FB7  BLM21PG121SN1  [0805]
FB8  BLM21PG121SN1  [0805]
FB9  BLM21PG121SN1  [0805]
J41  USB_A_2  [con_usb_a_2]
L1  90ohm  [ind_cm_2012]
L2  90ohm  [ind_cm_2012]
Q3  IRLML6346  [sot23]
Q4  IRLML6346  [sot23]
R155  10K  [0402]
R156  10K  [0402]
R157  0  [0402]
R158  100K  [0402]
R159  100K  [0402]
R160  0  [0402]
R161  1K  [0402]
R162  1K  [0402]
R163  51.1K  [0402]
R164  51.1K  [0402]
R165  18.2K  [0402]
R166  18.2K  [0402]
R167  0  [0402]
R168  0  [0402]
R169  0  [0402]
R170  0  [0402]
R171  10K  [0402]
R172  49.9  [0402]
R173  49.9  [0402]
R814  49.9  [0402]
R951  26.7K  [0402]
U37  MAX1558H  [dfn_p050_d040_b300_10_e230x150]
U38  VBUS054B-HSF  [tvs_llp75_6l]
sheet 11 Proc Pwr
C137  10uF  [0603]
C138  2.2uF  [0402]
C139  0.01uF  [0402]
C140  10uF  [0603]
C141  10uF  [0603]
C142  10uF  [0603]
C143  10uF  [0603]
C144  10uF  [0603]
C145  10uF  [0603]
C146  10uF  [0603]
C147  0.1uF  [0201]
C148  0.1uF  [0201]
C149  2.2uF  [0402]
C150  0.1uF  [0402]
C151  0.1uF  [0402]
C152  0.1uF  [0402]
C153  0.1uF  [0402]
C154  0.1uF  [0402]
C155  0.1uF  [0402]
C156  0.1uF  [0402]
C157  0.1uF  [0402]
C158  0.1uF  [0201]
C159  0.1uF  [0201]
C160  3000pF  [0402]
C161  2.2uF  [0402]
C162  2.2uF  [0402]
C163  0.01uF  [0402]
C164  0.01uF  [0402]
C165  0.01uF  [0402]
C166  0.01uF  [0402]
C167  0.01uF  [0402]
C168  0.01uF  [0402]
C169  0.01uF  [0402]
C170  0.1uF  [0201]
C171  0.1uF  [0201]
C172  3000pF  [0402]
C173  2.2uF  [0402]
C174  2.2uF  [0402]
C175  10uF  [0603]
C176  0.1uF  [0201]
C177  0.1uF  [0201]
C178  10uF  [0603]
C179  0.1uF  [0201]
C180  0.1uF  [0201]
C181  10uF  [0603]
C182  0.1uF  [0201]
C183  0.1uF  [0201]
C184  0.1uF  [0201]
C185  0.1uF  [0201]
C186  10uF  [0603]
C187  10uF  [0603]
C188  10uF  [0603]
C189  10uF  [0603]
C192  0.1uF  [0201]
C195  10uF  [0603]
C196  0.1uF  [0201]
C197  0.1uF  [0201]
C198  0.1uF  [0201]
C199  0.1uF  [0201]
C200  0.1uF  [0201]
C201  0.1uF  [0201]
C202  0.1uF  [0201]
C203  0.1uF  [0201]
C204  0.1uF  [0201]
C205  0.1uF  [0201]
C206  0.1uF  [0201]
C207  0.1uF  [0201]
C208  0.1uF  [0201]
C209  10uF  [0603]
C210  0.1uF  [0201]
C211  0.1uF  [0201]
C212  0.1uF  [0201]
C213  0.1uF  [0201]
C214  0.1uF  [0201]
C215  0.1uF  [0201]
C216  0.1uF  [0201]
C217  0.1uF  [0201]
C218  0.1uF  [0201]
C219  0.1uF  [0201]
C220  0.1uF  [0201]
C222  0.1uF  [0201]
C223  0.1uF  [0201]
C224  0.1uF  [0201]
C225  0.1uF  [0201]
C226  0.1uF  [0201]
C227  1500pF  [0201]
C228  1500pF  [0201]
C229  1500pF  [0201]
C230  1500pF  [0201]
C232  0.1uF  [0201]
C234  10uF  [0603]
C235  10uF  [0603]
C236  10uF  [0603]
C237  10uF  [0603]
C238  1uF  [0402]
C239  1uF  [0402]
C240  1uF  [0402]
C241  1uF  [0402]
C242  2.2uF  [0402]
C243  2.2uF  [0402]
C244  3000pF  [0402]
C245  0.1uF  [0201]
C246  0.1uF  [0201]
C247  0.1uF  [0201]
C248  0.1uF  [0201]
C249  2.2uF  [0402]
C250  2.2uF  [0402]
C251  3000pF  [0402]
C252  0.1uF  [0201]
C253  0.1uF  [0201]
C254  0.1uF  [0201]
C255  0.1uF  [0201]
C904  10uF  [0603]
C905  10uF  [0603]
C906  10uF  [0603]
C907  10uF  [0603]
C908  10uF  [0603]
C909  10uF  [0603]
C910  10uF  [0603]
C911  10uF  [0603]
C912  1uF  [0402]
C913  1uF  [0402]
C914  1uF  [0402]
C915  1uF  [0402]
C916  0.1uF  [0201]
C917  0.1uF  [0201]
C918  0.1uF  [0201]
C919  0.1uF  [0201]
C920  1500pF  [0201]
C921  1500pF  [0201]
C922  1500pF  [0201]
C923  1500pF  [0201]
C1003  1500pF  [0201]
C1004  1500pF  [0201]
C1005  1500pF  [0201]
C1006  1500pF  [0201]
C1007  1500pF  [0201]
C1008  1500pF  [0201]
C1009  1500pF  [0201]
C1010  1500pF  [0201]
C1011  0.1uF  [0201]
C1012  0.1uF  [0201]
C1013  NFM21PC225B0J3  [nfm21]
C1014  NFM21PC225B0J3  [nfm21]
C1026  0.1uF  [0201]
C1027  0.1uF  [0201]
C1028  0.1uF  [0201]
C1029  0.1uF  [0201]
C1030  0.1uF  [0201]
C1031  0.1uF  [0201]
C1032  0.1uF  [0201]
C1033  0.1uF  [0201]
C1034  0.1uF  [0201]
C1035  0.1uF  [0201]
C1036  0.1uF  [0201]
C1037  0.1uF  [0201]
C1038  0.1uF  [0201]
C1039  0.1uF  [0201]
C1114  0.1uF  [0201]
C1262  3000pF  [0402]
FB11  BLM18PG121SN1  [0603]
FB12  BLM18PG121SN1  [0603]
FB13  BLM18PG121SN1  [0603]
J9  JMP2  [jmp_p254_t_1x2]
J10  JMP2  [jmp_p254_t_1x2]
J11  JMP2  [jmp_p254_t_1x2]
R177  330  [0402]
R178  330  [0402]
R179  330  [0402]
TP15  TP  [tp]
TP16  TP  [tp]
TP17  TP  [tp]
TP18  TP  [tp]
sheet 12 Proc Gnd
C257  10uF  [0603]
C258  1uF  [0402]
C259  3000pF  [0402]
C260  4.7uF  [0603]
C261  47uF  [0805]
C264  3000pF  [0402]
C265  4.7uF  [0603]
C266  47uF  [0805]
C267  10uF  [0603]
C268  1uF  [0402]
C269  10uF  [0603]
C270  1uF  [0402]
C1263  10uF  [0603]
C1264  1uF  [0402]
R188  5.1  [0402]
R189  0.33  [0402]
R190  0  [0402]
R192  0.33  [0402]
R193  0  [0402]
R194  5.1  [0402]
R195  5.1  [0402]
R875  4.7K  [0402]
R876  4.7K  [0402]
R877  4.7K  [0402]
R878  4.7K  [0402]
R879  4.7K  [0402]
R880  0  [0402]
R881  4.7K  [0402]
R882  0  [0402]
R939  5.1  [0402]
sheet 13 UART&I2C
C271  0.1uF  [0402]
C272  0.1uF  [0402]
C273  0.1uF  [0402]
C274  0.1uF  [0402]
C275  0.1uF  [0402]
C276  100pF  [0402]
C277  100pF  [0402]
C278  100pF  [0402]
C279  100pF  [0402]
C284  0.1uF  [0402]
C285  0.1uF  [0402]
C286  0.1uF  [0402]
C287  0.1uF  [0402]
C288  0.1uF  [0402]
C289  100pF  [0402]
C290  100pF  [0402]
C291  100pF  [0402]
C292  100pF  [0402]
C293  0.1uF  [0402]
C294  1000pF  [0402]
C295  0.1uF  [0402]
C1115  0.1uF  [0402]
C1116  10uF  [0603]
FB18  BLM18BD601SN1  [0603]
FB19  BLM18BD601SN1  [0603]
FB20  BLM18BD601SN1  [0603]
FB21  BLM18BD601SN1  [0603]
FB22  BLM18BD601SN1  [0603]
FB23  BLM18BD601SN1  [0603]
FB24  BLM18BD601SN1  [0603]
FB25  BLM18BD601SN1  [0603]
J13  RJ45_2X1  [con_rj45_2x1]  (sections A,B)
J49  BAT_SOCKET  [con_bat_wba3b2]
R196  100  [0402]
R197  100  [0402]
R198  100  [0402]
R199  100  [0402]
R200  100  [0402]
R201  100  [0402]
R202  100  [0402]
R203  100  [0402]
R204  4.7K  [0402]
R205  100  [0402]
R206  100  [0402]
R853  4.7K  [0402]
R883  1K  [0402]
R940  4.7K  [0402]
U39  MAX3232  [tssop_16]
U41  MAX3232  [tssop_16]
U43  LCDA15C-8  [so_16]
U44  AT24C256  [so_8]
U45  ADT7461  [msop_8]
U100  DS1339U-33+  [msop_8]
Y6  32.768KHz  [cry_69x14_4]
sheet 14 EC1 PHY
C328  0.01uF  [0402]
C329  0.1uF  [0402]
C330  0.01uF  [0402]
C331  10pF  [0402]
C332  0.01uF  [0402]
C333  0.01uF  [0402]
C334  1000pF  [1206]
C335  10pF  [0402]
C336  1000pF  [1206]
C337  470pF  [0402]
C338  470pF  [0402]
C339  4.7pF  [0402]
C340  4.7pF  [0402]
C341  1000pF  [0402]
C342  1000pF  [1206]
C343  4.7uF  [0603]
C344  0.1uF  [0402]
C346  0.1uF  [0402]
C347  0.1uF  [0402]
C348  0.1uF  [0402]
C349  0.1uF  [0402]
C350  0.1uF  [0402]
C351  0.1uF  [0402]
C353  0.1uF  [0402]
C354  0.1uF  [0402]
C355  0.1uF  [0402]
C356  4.7uF  [0603]
C357  0.1uF  [0402]
C358  0.1uF  [0402]
FB29  BLM18BD601SN1  [0603]
FB60  BLM15AG601SN1  [0402]
FB61  BLM15AG601SN1  [0402]
J14  RJ45_LED_2X1  [con_rj45_2x1_led]  (sections A,B)
L4  2.2uH  [ind_swpa2520]
R236  75  [0603]
R237  75  [0603]
R238  33  [0402]
R239  33  [0402]
R240  75  [0603]
R241  75  [0603]
R242  33  [0402]
R243  33  [0402]
R244  33  [0402]
R245  33  [0402]
R246  33  [0402]
R247  510  [0402]
R248  510  [0402]
R249  100  [0402]
R250  0  [0402]
R251  0  [0402]
R252  4.7K  [0402]
R253  15  [0402]
R256  2.49K  [0402]
R257  4.7K  [0402]
R258  4.7K  [0402]
R259  4.7K  [0402]
R260  4.7K  [0402]
R261  4.7K  [0402]
R262  4.7K  [0402]
R263  4.7K  [0402]
R264  4.7K  [0402]
R825  0  [0402]
R826  0  [0402]
T2  GST5009LF  [mag_gst5009]
U49  RTL8211E-VB  [qfn_p040_d040_b600_48_e440]
U50  SRV05-4  [sot23_6]
U51  SRV05-4  [sot23_6]
Y2  25MHz  [cry_32x25_4]
sheet 15 EC2 PHY
C296  0.01uF  [0402]
C297  0.1uF  [0402]
C298  0.01uF  [0402]
C299  0.01uF  [0402]
C300  10pF  [0402]
C301  0.01uF  [0402]
C302  1000pF  [1206]
C303  10pF  [0402]
C304  4.7pF  [0402]
C305  4.7pF  [0402]
C307  470pF  [0402]
C308  470pF  [0402]
C309  1000pF  [0402]
C310  1000pF  [1206]
C312  4.7uF  [0603]
C313  0.1uF  [0402]
C314  0.1uF  [0402]
C315  0.1uF  [0402]
C316  0.1uF  [0402]
C317  0.1uF  [0402]
C319  0.1uF  [0402]
C320  0.1uF  [0402]
C321  0.1uF  [0402]
C322  0.1uF  [0402]
C323  0.1uF  [0402]
C324  4.7uF  [0603]
C325  0.1uF  [0402]
C326  0.1uF  [0402]
FB26  BLM18BD601SN1  [0603]
FB62  BLM15AG601SN1  [0402]
FB63  BLM15AG601SN1  [0402]
L3  2.2uH  [ind_swpa2520]
R207  75  [0603]
R208  75  [0603]
R209  33  [0402]
R210  75  [0603]
R211  33  [0402]
R212  75  [0603]
R213  33  [0402]
R214  33  [0402]
R215  33  [0402]
R216  33  [0402]
R217  33  [0402]
R218  510  [0402]
R219  510  [0402]
R220  100  [0402]
R221  0  [0402]
R222  0  [0402]
R224  15  [0402]
R227  2.49K  [0402]
R228  4.7K  [0402]
R229  4.7K  [0402]
R230  4.7K  [0402]
R231  4.7K  [0402]
R232  4.7K  [0402]
R233  4.7K  [0402]
R234  4.7K  [0402]
R235  4.7K  [0402]
R822  0  [0402]
R823  4.7K  [0402]
R824  0  [0402]
T1  GST5009LF  [mag_gst5009]
U46  RTL8211E-VB  [qfn_p040_d040_b600_48_e440]
U47  SRV05-4  [sot23_6]
U48  SRV05-4  [sot23_6]
Y1  25MHz  [cry_32x25_4]

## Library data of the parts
U1 = T1024: AGILE_PN: 312-00102; TYPE: IC; Vendor: Freescale
C55 C56 C300 C303 C309 C331 C335 C341 = CAP: BOM_IGNORE: DNP; VOLTAGE: 50V
C57-C60 C67 C68 C93 C94 C131 C150-C157 C271-C275 C284-C288 C293 C295 C297 C313-C317 C319-C323 C325 C326 C329 C344 C346-C351 C353-C355 C357 C358 C1081 C1115 C1267 C1268 C1380 C1381 = CAP: AGILE_PN: 150-75663; VOLTAGE: 16V
R115-R122 R125-R130 = RES: AGILE_PN: 470-75589; TOL: 5%
R123 R124 R132 R204 R228-R235 R252 R257-R264 R823 R849-R853 R875-R879 R881 R940 = RES: AGILE_PN: 470-75626; TOL: 5%
R131 = RES: AGILE_PN: 470-76303; TOL: 5%
R133 R177-R179 = RES: AGILE_PN: 470-75613; TOL: 5%
R134 = RES: AGILE_PN: 470-00028; TOL: 5%
R138 R161 R162 R883 = RES: AGILE_PN: 470-75555; TOL: 5%
R139 = RES: AGILE_PN: 470-76255; TOL: 1%
R140 = RES: AGILE_PN: 470-76480; TOL: 1%
TP11-TP18 = TP: TYPE: PAD
U23 U24 = 74LVC1G66: AGILE_PN: 315-80500; MPN: SN74LVC1G66DCKR; TYPE: IC; Vendor: TI
C84 = CAP: AGILE_PN: 150-75016; VOLTAGE: 25V
C85 C139 C163-C169 C296 C298 C299 C301 C328 C330 C332 C333 = CAP: AGILE_PN: 150-75183; VOLTAGE: 25V
C92 C137 C140-C146 C175 C178 C181 C186-C189 C195 C209 C234-C237 C257 C267 C269 C904-C911 C1116 C1263 = CAP: AGILE_PN: 150-78675; VOLTAGE: 6.3V
C1080 = CAP_E: AGILE_PN: 150-78779; TYPE: CAP; VOLTAGE: 25V
J43 = CONN_2X20: AGILE_PN: 211-78482; MPN: MEC6-120-02-S-DV-A-K-TR; TYPE: CON; Vendor: Samtec
R867 R869 = RES: AGILE_PN: 470-76089; TOL: 5%
R209 R211 R213-R217 R238 R239 R242-R246 R868 = RES: AGILE_PN: 470-75790; TOL: 5%
C124 C127 = CAP_E: AGILE_PN: 150-00078; TYPE: CAP; VOLTAGE: 10V
C125 C128 C130 = CAP: AGILE_PN: 150-75283; VOLTAGE: 16V
C126 C129 C294 = CAP: AGILE_PN: 150-76334; VOLTAGE: 50V
C1022 = CAP: BOM_IGNORE: DNP; VOLTAGE: 16V
D3 D4 = DIODE: AGILE_PN: 480-78080; Vendor: Central
FB6-FB9 = BEAD: AGILE_PN: 180-78321; Vendor: Murata
J41 = USB_A_2: AGILE_PN: 210-00073; MPN: XUSB-6-7-4-3-1-3-05; TYPE: CON; Vendor: XMULTIPLE
L1 L2 = IND_CM: AGILE_PN: 180-76336; MPN: DLW21HN900SQ2L; TYPE: IND; Vendor: Murata
Q3 Q4 = NMOS: BOM_IGNORE: DNP; MPN: IRLML6346TRPBF; TYPE: MOS; Vendor: IR
R155 R156 R167-R170 R224 R880 R882 = RES: BOM_IGNORE: DNP; TOL: 5%
R157 R160 R190 R193 R221 R222 R250 R251 R822 R824-R826 = RES: AGILE_PN: 470-75394; TOL: 5%
R158 R159 = RES: AGILE_PN: 470-75597; TOL: 5%
R163 R164 = RES: AGILE_PN: 470-31028; TOL: 1%
R165 R166 = RES: AGILE_PN: 470-76207; TOL: 1%
R171 = RES: AGILE_PN: 470-75416; TOL: 1%
R172 R173 = RES: AGILE_PN: 470-75360; TOL: 1%
R814 = RES: BOM_IGNORE: DNP; TOL: 1%
R951 = RES: AGILE_PN: 470-00154; TOL: 1%
U37 = MAX1558H: AGILE_PN: 312-80581; MPN: MAX1558HETB+; TYPE: IC; Vendor: Maxim
U38 = SRV05-4: AGILE_PN: 312-77957; MPN: VBUS054B-HSF-GS08; TYPE: IC; Vendor: Vishay
C138 C149 C162 C242 C249 = CAP: AGILE_PN: 150-00094; VOLTAGE: 4V
C147 C148 C158 C159 C170 C171 C176 C177 C179 C180 C182-C185 C192 C196-C208 C210-C220 C222-C226 C232 C238-C241 C245-C248 C252-C255 C258 C268 C270 C912-C919 C1011 C1012 C1026-C1039 C1114 C1264 = CAP: AGILE_PN: 150-75421; VOLTAGE: 6.3V
C160 C172 C244 C251 C259 C264 C1262 = CAP: AGILE_PN: 150-00075; VOLTAGE: 50V
C161 C173 C174 C243 C250 = CAP: AGILE_PN: 150-76792; VOLTAGE: 4V
C227-C230 C920-C923 C1003-C1010 = CAP: AGILE_PN: 150-00094; VOLTAGE: 25V
C1013 C1014 = CAP_3T_4P: AGILE_PN: 150-00084; TYPE: CAP; Vendor: Murata
FB11-FB13 = BEAD: AGILE_PN: 180-30008; Vendor: Murata
J9-J11 = JMP2: AGILE_PN: 210-80733; MPN: TSW-102-07-F-S; TYPE: HDR; Vendor: Samtec
C260 C265 C312 C324 C343 C356 = CAP: AGILE_PN: 150-75487; VOLTAGE: 6.3V
C261 C266 = CAP: AGILE_PN: 150-79458; VOLTAGE: 6.3V
R188 R194 R195 R939 = RES: AGILE_PN: 470-00060; TOL: 5%
R189 R192 = RES: AGILE_PN: 470-00114; TOL: 1%
C276-C279 C289-C292 = CAP: AGILE_PN: 150-30247; VOLTAGE: 50V
FB18-FB26 FB29 = BEAD: AGILE_PN: 180-75046; Vendor: Murata
J13 = RJ45_2X1: AGILE_PN: 210-79733; MPN: 10118069-500B010LF; TYPE: CON; Vendor: FCI
J49 = BAT_SOCKET: AGILE_PN: 801-75534; MPN: WBA3B2 U; TYPE: CON; Vendor: WIN WIN PRECISION INDUSTRIAL
R196-R203 R205 R206 R220 R249 = RES: AGILE_PN: 470-30454; TOL: 5%
U39 U41 = MAX3232: AGILE_PN: 312-79542; MPN: ICL3232IVZ; TYPE: IC; Vendor: Intersil
U43 = LCDA15C-8: BOM_IGNORE: DNP; MPN: LCDA15C-8.TBT; TYPE: IC; Vendor: Semtech
U44 = EEPROM-I2C: AGILE_PN: 334-77611; MPN: AT24C256C-SSHL-B; TYPE: IC; Vendor: Atmel
U45 = ADT7461: AGILE_PN: 315-75543; MPN: ADT7461ARMZ-R7; TYPE: IC; Vendor: ON Semi
U100 = DS1339U: AGILE_PN: 315-76726; TYPE: IC; Vendor: Maxim
Y6 = CRYSTAL_32K: AGILE_PN: 230-00040; MPN: 6.9x1.4mm,4pin,+/-20ppm; TYPE: XTAL
C302 C310 C334 C336 C342 = CAP: AGILE_PN: 150-00046; VOLTAGE: 2KV
C307 C308 C337 C338 = CAP: AGILE_PN: 150-75452; VOLTAGE: 50V
C304 C305 C339 C340 = CAP: AGILE_PN: 150-75273; VOLTAGE: 50V
FB60-FB63 = BEAD: AGILE_PN: 180-00046; Vendor: Murata
J14 = RJ45_LED_2X1: AGILE_PN: 210-79574; MPN: 10118075-510B010LF; TYPE: CON; Vendor: FCI
L3 L4 = IND_IRON: AGILE_PN: 180-78317; MPN: SWPA252012S2R2MT; TYPE: IND; Vendor: Sunlord
R207 R208 R210 R212 R236 R237 R240 R241 = RES: AGILE_PN: 470-75826; TOL: 5%
R218 R219 R247 R248 = RES: AGILE_PN: 470-80835; TOL: 5%
R253 = RES: BOM_IGNORE: DNP; VOLTAGE: 50V
R256 = RES: AGILE_PN: 470-30876; TOL: 1%
T1 T2 = H5004: TYPE: XFMR; Vendor: Bothhand
U46 U49 = RTL8211E-VB: AGILE_PN: 312-80808; MPN: RTL8211E-VB-CG; TYPE: IC; Vendor: Realtek
U47 U48 U50 U51 = SRV05-4: BOM_IGNORE: DNP; MPN: SRV05-4.TCT; TYPE: IC; Vendor: Semtech
Y1 Y2 = CRYSTAL_4PIN_v2: AGILE_PN: 230-77947; MPN: 3.2x2.5mm,4pin,CL=18pF,+/-20ppm; TYPE: XTAL
R227 = RES: AGILE_PN: 470-30877; TOL: 1%

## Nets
1V0_FA_VL: C222.1 J11.1 R179.2 U1.G18(FA_VL)
1V0_USB_SVDD: C138.1 C147.1 C148.1 C149.1 C1262.1 FB11.1 U1.K9(USB_SVDD1) U1.K10(USB_SVDD2)
1V0S: C1013.2 ; also on sheet 27
1V2: C1114.1 R133.1 R134.1 U1.T6(TVDD) ; also on sheet 1 2 18 19 25
1V05_EC1_AVDD: C343.1 C344.1 C353.1 C354.1 C355.1 L4.2 R826.2 U49.3(AVDD10) U49.9(AVDD10) U49.40(AVDD10)
1V05_EC1_DVDD: C348.1 C349.1 R826.1 U49.28(DVDD10) U49.36(DVDD10)
1V05_EC2_AVDD: C312.1 C313.1 C321.1 C322.1 C323.1 L3.2 R824.2 U46.3(AVDD10) U46.9(AVDD10) U46.40(AVDD10)
1V05_EC2_DVDD: C316.1 C317.1 R824.1 U46.28(DVDD10) U46.36(DVDD10)
1V8: C195.1 C196.1 C197.1 C198.1 C199.1 C232.1 C1011.1 C1012.1 FB13.2 R188.1 R195.1 R939.1 U1.G9(TH_VDD) U1.J14(OVDD1) U1.J15(OVDD2) U1.J16(OVDD3) U1.J17(OVDD4) U1.J18(OVDD5) U1.J19(OVDD6) ; also on sheet 6 7 8 9 22 23 27
1V8_MTR: C208.1 J10.1 R178.2 U1.F11(PROG_MTR)
1V8_SFP: C192.1 J9.1 R177.2 U1.F12(PROG_SFP)
1V8_SLP: C209.1 C210.1 C211.1 C220.1 J9.2 J10.2 R194.1 R876.2 R877.2 R878.2 R879.2 U1.J11(O1VDD1) U1.J12(O1VDD2) U1.J13(O1VDD3) ; also on sheet 9 22 23 24 26 27
1V8_USB_OVDD: C170.1 C171.1 C172.1 C173.1 C174.1 FB13.1 U1.J9(USB_OVDD1) U1.J10(USB_OVDD2)
1V35: C137.1 C139.1 C140.1 C141.1 C142.1 C143.1 C144.1 C145.1 C146.1 C150.1 C151.1 C152.1 C153.1 C154.1 C155.1 C156.1 C157.1 C163.1 C164.1 C165.1 C166.1 C167.1 C168.1 C169.1 C1014.1 R189.2 R192.2 U1.AA27(G1VDD17) U1.AD27(G1VDD18) U1.AF27(G1VDD19) U1.D27(G1VDD01) U1.F27(G1VDD02) U1.H27(G1VDD03) U1.K21(G1VDD04) U1.K27(G1VDD05) U1.L21(G1VDD06) U1.M21(G1VDD07) U1.M27(G1VDD08) U1.N21(G1VDD09) U1.P21(G1VDD10) U1.P27(G1VDD11) U1.R21(G1VDD12) U1.T21(G1VDD13) U1.U21(G1VDD14) U1.U27(G1VDD15) U1.W27(G1VDD16) ; also on sheet 5 27
2V5: C175.1 C176.1 C177.1 C314.1 C315.1 R138.2 R229.2 R230.2 R231.2 R232.2 U1.V8(LVDD1) U1.W8(LVDD2) U46.15(DVDD33) U46.21(DVDD33) ; also on sheet 1 2 18 19 20 27
2V5_SLP: C57.1 C58.1 C178.1 C179.1 C180.1 C346.1 C347.1 R131.1 R132.1 R258.2 R259.2 R260.2 R875.1 R881.1 U1.T8(L1VDD1) U1.U8(L1VDD2) U23.5(VCC) U24.5(VCC) U49.15(DVDD33) U49.21(DVDD33) ; also on sheet 9 26 27
3V3: C92.1 C93.1 C94.1 C181.1 C182.1 C183.1 C184.1 C272.1 C286.1 C293.1 C319.1 C320.1 C324.1 C325.1 C326.1 C1028.1 C1081.1 FB12.2 FB26.1 J43.10 J43.12 J43.14 J43.16 R155.2 R156.2 R158.2 R159.2 R234.2 R235.2 R822.1 R823.1 R849.1 R850.1 R851.1 R852.1 U1.M8(CVDD) U1.N8(DVDD1) U1.P8(DVDD2) U1.R8(DVDD3) U39.16(VCC) U41.16(VCC) U44.8(VCC) U46.6(AVDD33) U46.37(DVDD33) U46.41(AVDD33) U46.44(VDDREG) U46.45(VDDREG) ; also on sheet 7 8 9 21 23 24 27
3V3_SLP: C295.1 C350.1 C351.1 C356.1 C357.1 C358.1 C1115.1 FB29.1 R204.2 R252.1 R263.2 R264.2 R825.1 R853.2 R940.2 U45.1(VDD) U49.6(AVDD33) U49.37(DVDD33) U49.41(AVDD33) U49.44(VDDREG) U49.45(VDDREG) U100.8(VCC) ; also on sheet 5 9 22 25 26 27 28
3V3_USB_HVDD: C158.1 C159.1 C160.1 C161.1 C162.1 FB12.1 U1.J8(USB_HVDD1) U1.K8(USB_HVDD2)
5V0_SLP: C130.1 C131.1 U37.1(INA) U37.5(INB) U38.5 ; also on sheet 25 26 28
5V0_USB1: C127.1 C128.1 C129.1 D4.1 FB6.2 R164.2 U37.10(OUTA)
5V0_USB2: C124.1 C125.1 C126.1 D3.1 FB8.2 R163.2 U37.6(OUTB)
12V: C84.1 C85.1 C1080.1 J43.2 J43.4 J43.6 ; also on sheet 21 27 28
AGND_SD1_PLL1: C259.2 C260.2 C261.2 R190.1 U1.AA16(SD_GND07)
AGND_SD1_PLL2: C264.2 C265.2 C266.2 R193.1 U1.AA20(SD_GND10)
AVDD_CGA1: C257.1 C258.1 R188.2 U1.G11(AVDD_CGA1)
AVDD_CGA2: C1263.1 C1264.1 R939.2 U1.G12(NC)
AVDD_DDR1: C269.1 C270.1 R195.2 U1.E20(AVDD_D1)
AVDD_PLAT: C267.1 C268.1 R194.2 U1.G10(AVDD_PLAT)
AVDD_SD1_PLL1: C259.1 C260.1 C261.1 R189.1 U1.AB16(AVDD_SD1_PLL1)
AVDD_SD1_PLL2: C264.1 C265.1 C266.1 R192.1 U1.AB20(AVDD_SD1_PLL2)
GND: C55.1 C56.2 C57.2 C58.2 C84.2 C85.2 C92.2 C93.2 C94.2 C124.2 C125.2 C126.2 C127.2 C128.2 C129.2 C130.2 C131.2 C137.2 C138.2 C139.2 C140.2 C141.2 C142.2 C143.2 C144.2 C145.2 C146.2 C147.2 C148.2 C149.2 C150.2 C151.2 C152.2 C153.2 C154.2 C155.2 C156.2 C157.2 C158.2 C159.2 C160.2 C161.2 C162.2 C163.2 C164.2 C165.2 C166.2 C167.2 C168.2 C169.2 C170.2 C171.2 C172.2 C173.2 C174.2 C175.2 C176.2 C177.2 C178.2 C179.2 C180.2 C181.2 C182.2 C183.2 C184.2 C185.2 C186.2 C187.2 C188.2 C189.2 C192.2 C195.2 C196.2 C197.2 C198.2 C199.2 C200.2 C201.2 C202.2 C203.2 C204.2 C205.2 C206.2 C207.2 C208.2 C209.2 C210.2 C211.2 C212.2 C213.2 C214.2 C215.2 C216.2 C217.2 C218.2 C219.2 C220.2 C222.2 C223.2 C224.2 C225.2 C226.2 C227.2 C228.2 C229.2 C230.2 C232.2 C234.2 C235.2 C236.2 C237.2 C238.2 C239.2 C240.2 C241.2 C242.2 C243.2 C244.2 C245.2 C246.2 C247.2 C248.2 C249.2 C250.2 C251.2 C252.2 C253.2 C254.2 C255.2 C257.2 C258.2 C267.2 C268.2 C269.2 C270.2 C272.2 C273.2 C275.2 C276.2 C277.2 C278.2 C279.2 C286.2 C287.2 C288.2 C289.2 C290.2 C291.2 C292.2 C293.2 C295.2 C296.1 C297.2 C298.1 C299.1 C300.1 C301.1 C303.2 C304.2 C305.2 C307.2 C308.2 C309.2 C310.1 C312.2 C313.2 C314.2 C315.2 C316.2 C317.2 C319.2 C320.2 C321.2 C322.2 C323.2 C324.2 C325.2 C326.2 C328.1 C329.2 C330.1 C331.1 C332.1 C333.1 C335.2 C336.1 C337.2 C338.2 C339.2 C340.2 C341.2 C342.1 C343.2 C344.2 C346.2 C347.2 C348.2 C349.2 C350.2 C351.2 C353.2 C354.2 C355.2 C356.2 C357.2 C358.2 C904.2 C905.2 C906.2 C907.2 C908.2 C909.2 C910.2 C911.2 C912.2 C913.2 C914.2 C915.2 C916.2 C917.2 C918.2 C919.2 C920.2 C921.2 C922.2 C923.2 C1003.2 C1004.2 C1005.2 C1006.2 C1007.2 C1008.2 C1009.2 C1010.2 C1011.2 C1012.2 C1013.3 C1013.4 C1014.3 C1014.4 C1026.2 C1027.2 C1028.2 C1029.2 C1030.2 C1031.2 C1032.2 C1033.2 C1034.2 C1035.2 C1036.2 C1037.2 C1038.2 C1039.2 C1080.2 C1081.2 C1114.2 C1115.2 C1116.2 C1262.2 C1263.2 C1264.2 FB7.2 FB9.2 J13.A4 J13.A5 J13.B4 J13.B5 J14.A10 J14.B10 J43.5 J43.15 J43.19 J43.23 J43.26 J43.30 J43.37 J43.40 J49.2 Q3.2(S) Q4.2(S) R123.1 R124.2 R161.1 R162.1 R165.1 R166.1 R171.1 R172.1 R173.1 R177.1 R178.1 R179.1 R190.2 R193.2 R227.1 R228.2 R233.2 R256.1 R257.2 R261.2 R262.2 R814.1 R951.1 U1.A2(GND001) U1.A20(GND002) U1.A27(GND003) U1.AA7(GND148) U1.AA11(GND149) U1.AA13(SD_GND05) U1.AA15(SD_GND06) U1.AA17(SD_GND08) U1.AA19(SD_GND09) U1.AA21(SD_GND11) U1.AA24(GND150) U1.AB2(GND151) U1.AB5(GND152) U1.AB7(GND153) U1.AB13(SD_GND12) U1.AB17(SD_GND13) U1.AB21(SD_GND14) U1.AB22(GND154) U1.AB26(GND155) U1.AC1(NC) U1.AC2(NC) U1.AC10(NC) U1.AC11(NC) U1.AC13(SD_GND15) U1.AC14(SD_GND16) U1.AC16(SD_GND17) U1.AC17(SD_GND18) U1.AC19(SD_GND19) U1.AC20(SD_GND20) U1.AC24(GND156) U1.AC26(GND157) U1.AD4(GND158) U1.AD6(GND159) U1.AD9(NC) U1.AD12(NC) U1.AD15(SD_GND21) U1.AD18(SD_GND22) U1.AD21(SD_GND23) U1.AD22(GND160) U1.AE2(GND161) U1.AE9(NC) U1.AE12(NC) U1.AE15(SD_GND24) U1.AE18(SD_GND25) U1.AE21(SD_GND26) U1.AE24(GND162) U1.AE26(GND163) U1.AF9(GND164) U1.AF10(NC) U1.AF11(NC) U1.AF12(NC) U1.AF13(NC) U1.AF14(NC) U1.AF15(SD_GND27) U1.AF16(SD_GND28) U1.AF17(SD_GND29) U1.AF18(SD_GND30) U1.AF19(SD_GND31) U1.AF20(SD_GND32) U1.AF21(GND165) U1.AG1(GND166) U1.AG4(GND167) U1.AG6(GND168) U1.AG9(NC) U1.AG10(NC) U1.AG11(NC) U1.AG12(NC) U1.AG13(NC) U1.AG14(NC) U1.AG15(SD_GND33) U1.AG18(SD_GND34) U1.AG21(SD_GND35) U1.AG22(GND169) U1.AG23(GND170) U1.AG26(GND171) U1.AH2(GND172) U1.AH9(NC) U1.AH10(NC) U1.AH11(NC) U1.AH12(NC) U1.AH13(NC) U1.AH14(NC) U1.AH15(SD_GND36) U1.AH18(SD_GND37) U1.AH21(SD_GND38) U1.B1(GND004) U1.B4(GND005) U1.B7(GND006) U1.B10(GND007) U1.B13(GND008) U1.B16(GND009) U1.B19(GND010) U1.B23(GND011) U1.B25(GND012) U1.B28(GND013) U1.C22(GND014) U1.C26(GND015) U1.D2(GND016) U1.D20(GND017) U1.D21(GND018) U1.D24(GND019) U1.E1(USB_AGND01) U1.E2(USB_AGND02) U1.E3(USB_AGND03) U1.E5(GND020) U1.E7(GND021) U1.E10(GND022) U1.E13(GND023) U1.E16(GND024) U1.E19(GND025) U1.E22(GND026) U1.E26(GND027) U1.F3(USB_AGND04) U1.F15(GND028) U1.F24(GND029) U1.G1(USB_AGND05) U1.G2(USB_AGND06) U1.G3(USB_AGND07) U1.G5(USB_AGND08) U1.G7(GND030) U1.G13(GND031) U1.G16(GND032) U1.G22(GND033) U1.G26(GND034) U1.H3(USB_AGND09) U1.H7(GND035) U1.H8(GND036) U1.H9(GND037) U1.H10(GND038) U1.H11(GND039) U1.H12(GND040) U1.H13(GND041) U1.H14(GND042) U1.H15(GND043) U1.H16(GND044) U1.H17(GND045) U1.H18(GND046) U1.H19(GND047) U1.H20(GND048) U1.H24(GND049) U1.J1(USB_AGND10) U1.J2(USB_AGND11) U1.J3(USB_AGND12) U1.J7(GND050) U1.J22(GND051) U1.J26(GND052) U1.K2(GND053) U1.K5(GND054) U1.K6(GND055) U1.K7(GND056) U1.K12(GND057) U1.K14(GND058) U1.K16(GND059) U1.K18(GND060) U1.K20(GND061) U1.K24(GND062) U1.L7(GND063) U1.L9(GND064) U1.L11(GND065) U1.L13(GND066) U1.L15(GND067) U1.L17(GND068) U1.L19(GND069) U1.L22(GND070) U1.L26(GND071) U1.M7(GND072) U1.M10(GND073) U1.M12(GND074) U1.M14(GND075) U1.M16(GND076) U1.M18(GND077) U1.M20(GND078) U1.M24(GND079) U1.N2(GND080) U1.N5(GND081) U1.N7(GND082) U1.N9(GND083) U1.N11(GND084) U1.N13(GND085) U1.N15(GND086) U1.N17(GND087) U1.N19(GND088) U1.N22(GND089) U1.N26(GND090) U1.P7(GND091) U1.P10(GND092) U1.P12(GND093) U1.P14(GND094) U1.P16(GND095) U1.P18(GND096) U1.P20(GND097) U1.P24(GND098) U1.R7(GND099) U1.R9(GND100) U1.R11(GND101) U1.R13(GND102) U1.R15(GND103) U1.R17(GND104) U1.R19(GND105) U1.R22(GND106) U1.R26(GND107) U1.T2(GND108) U1.T5(GND109) U1.T7(GND110) U1.T10(GND111) U1.T12(GND112) U1.T14(GND113) U1.T16(GND114) U1.T18(GND115) U1.T20(GND116) U1.T22(GND117) U1.T26(GND118) U1.U7(GND119) U1.U9(GND120) U1.U11(GND121) U1.U13(GND122) U1.U15(GND123) U1.U17(GND124) U1.U19(GND125) U1.U24(GND126) U1.V7(GND127) U1.V10(GND128) U1.V12(GND129) U1.V14(GND130) U1.V16(GND131) U1.V18(GND132) U1.V20(GND133) U1.V22(GND134) U1.V26(GND135) U1.W2(GND136) U1.W5(GND137) U1.W7(GND138) U1.W9(GND139) U1.W11(GND140) U1.W13(GND141) U1.W24(GND142) U1.Y7(GND143) U1.Y10(GND144) U1.Y12(GND145) U1.Y14(SD_GND01) U1.Y16(SD_GND02) U1.Y17(SD_GND03) U1.Y18(SD_GND04) U1.Y22(GND146) U1.Y26(GND147) U23.3(GND) U24.3(GND) U37.8(GND) U37.11(EPAD) U38.2 U39.15(GND) U41.15(GND) U43.9 U43.10 U43.11 U43.12 U43.13 U43.14 U43.15 U43.16 U44.1(A0) U44.2(A1) U44.3(A2) U44.4(GND) U44.7(WP) U45.5(GND) U46.47(GND) U46.49(EPAD) U47.2 U48.2 U49.47(GND) U49.49(EPAD) U50.2 U51.2 U100.4(GND) Y1.2 Y1.4 Y2.2 Y2.4 Y6.2 Y6.3 ; also on sheet 1 2 5 6 7 8 9 18 19 20 21 22 23 24 25 26 27 28 29
SVDD: C242.1 C243.1 C244.1 C245.1 C246.1 C247.1 C248.1 C1013.1 C1027.1 R139.1 U1.W15(S1VDD1) U1.W16(S1VDD2) U1.W17(S1VDD3) U1.W18(S1VDD4) U1.W19(S1VDD5) U1.W20(S1VDD6) U1.Y13(S1VDD7)
EARTH: C302.2 C310.2 C334.2 C336.2 C342.2 J13.17 J13.18 J13.19 J13.20 J13.21 J13.22 J14.25 J14.26 J14.27 J14.28 J41.9 J41.10 J41.11 J41.12 ; also on sheet 20 29
EC1_GTXCLK: R127.1 U49.22(TXC)
EC1_INT_N: R250.2 ; also on sheet 9
EC1_LED0: R247.1 R262.1 U49.34(LED0/PHY_AD0)
EC1_LED1: R248.1 R263.1 U49.35(LED1/PHY_AD1)
EC1_MDI0_N: T2.11 U49.2(MDI-[0]) U50.1
EC1_MDI0_P: T2.12 U49.1(MDI+[0]) U50.3
EC1_MDI1_N: T2.8 U49.5(MDI-[1]) U50.6
EC1_MDI1_P: T2.9 U49.4(MDI+[1]) U50.4
EC1_MDI2_N: T2.5 U49.8(MDI-[2]) U51.1
EC1_MDI2_P: T2.6 U49.7(MDI+[2]) U51.3
EC1_MDI3_N: T2.2 U49.11(MDI-[3]) U51.6
EC1_MDI3_P: T2.3 U49.10(MDI+[3]) U51.4
EC1_MDX0_N: J14.B2 T2.14
EC1_MDX0_P: J14.B1 T2.13
EC1_MDX1_N: J14.B6 T2.17
EC1_MDX1_P: J14.B3 T2.16
EC1_MDX2_N: J14.B5 T2.20
EC1_MDX2_P: J14.B4 T2.19
EC1_MDX3_N: J14.B8 T2.23
EC1_MDX3_P: J14.B7 T2.22
EC1_PME_N: R251.2 ; also on sheet 9 22
EC1_REFCLK: R246.2 U1.AG3(EC1_GTX_CLK125)
EC1_RST_N: R249.1 R252.2 ; also on sheet 22
EC1_RXCLK: R238.1 U1.AD1(EC1_RX_CLK)
EC1_RXCTL: R245.1 R261.1 U1.AG2(EC1_RX_DV)
EC1_RXD0: R239.1 R257.1 U1.AF2(EC1_RXD0)
EC1_RXD1: R242.1 R258.1 U1.AF1(EC1_RXD1)
EC1_RXD2: R243.1 R259.1 U1.AE1(EC1_RXD2)
EC1_RXD3: R244.1 R260.1 U1.AD2(EC1_RXD3)
EC1_RXDLY: R264.1 U49.32(LED2/RXDLY)
EC1_TXCTL: R125.1 U49.27(TXCTL)
EC1_TXD0: R115.1 U49.23(TXD0)
EC1_TXD1: R116.1 U49.24(TXD1)
EC1_TXD2: R119.1 U49.25(TXD2)
EC1_TXD3: R121.1 U49.26(TXD3)
EC2_GTXCLK: R128.2 U46.22(TXC)
EC2_INT_N: R221.2 ; also on sheet 9
EC2_LED0: R218.1 R233.1 U46.34(LED0/PHY_AD0)
EC2_LED1: R219.1 R234.1 U46.35(LED1/PHY_AD1)
EC2_MDI0_N: T1.11 U46.2(MDI-[0]) U47.1
EC2_MDI0_P: T1.12 U46.1(MDI+[0]) U47.3
EC2_MDI1_N: T1.8 U46.5(MDI-[1]) U47.6
EC2_MDI1_P: T1.9 U46.4(MDI+[1]) U47.4
EC2_MDI2_N: T1.5 U46.8(MDI-[2]) U48.1
EC2_MDI2_P: T1.6 U46.7(MDI+[2]) U48.3
EC2_MDI3_N: T1.2 U46.11(MDI-[3]) U48.6
EC2_MDI3_P: T1.3 U46.10(MDI+[3]) U48.4
EC2_MDX0_N: J14.A2 T1.14
EC2_MDX0_P: J14.A1 T1.13
EC2_MDX1_N: J14.A6 T1.17
EC2_MDX1_P: J14.A3 T1.16
EC2_MDX2_N: J14.A5 T1.20
EC2_MDX2_P: J14.A4 T1.19
EC2_MDX3_N: J14.A8 T1.23
EC2_MDX3_P: J14.A7 T1.22
EC2_PME_N: R222.2 ; also on sheet 9
EC2_REFCLK: R217.2 U1.AE5(TSEC_1588_TRIG_IN2)
EC2_RST_N: R220.1 R823.2 ; also on sheet 22
EC2_RXCLK: R211.1 U1.AF5(TSEC_1588_ALARM_OUT1)
EC2_RXCTL: R216.1 R232.1 U1.AF8(GPIO3_24)
EC2_RXD0: R209.1 R228.1 U1.AE8(GPIO3_25)
EC2_RXD1: R213.1 R229.1 U1.AH7(GPIO3_28)
EC2_RXD2: R214.1 R230.1 U1.AE6(TSEC_1588_PULSE_OUT1)
EC2_RXD3: R215.1 R231.1 U1.AH6(GPIO3_27)
EC2_RXDLY: R235.1 U46.32(LED2/RXDLY)
EC2_TXCTL: R126.2 U46.27(TXCTL)
EC2_TXD0: R117.2 U46.23(TXD0)
EC2_TXD1: R118.2 U46.24(TXD1)
EC2_TXD2: R120.2 U46.25(TXD2)
EC2_TXD3: R122.2 U46.26(TXD3)
EMI1_MDC: U23.2(B) U46.30(MDC)
EMI1_MDC_SLP: R129.1 R132.2 U23.1(A) U49.30(MDC)
EMI1_MDIO: U24.2(B) U46.31(MDIO)
EMI1_MDIO_SLP: R131.2 U1.AH4(EMI1_MDIO) U24.1(A) U49.31(MDIO)
EMI2_MDC: R130.2 R134.2 ; also on sheet 2 18
EMI2_MDIO: R133.2 U1.V6(EMI2_MDIO) ; also on sheet 2 18
EVDD: C185.1 U1.L8(EVDD) ; also on sheet 8 27
I2C1_SCL: U44.6(SCL) ; also on sheet 9
I2C1_SCL_SLP: U45.8(SCLK) U100.6(SCL) ; also on sheet 5 9 24 25
I2C1_SDA: U44.5(SDA) ; also on sheet 9
I2C1_SDA_SLP: U45.7(SDATA) U100.5(SDA) ; also on sheet 5 9 24 25
MPEX1_RX_N: U1.AG19(SD1_RX2_N) ; also on sheet 21
MPEX1_RX_P: U1.AH19(SD1_RX2_P) ; also on sheet 21
MPEX1_TX_N: U1.AE19(SD1_TX2_N) ; also on sheet 21
MPEX1_TX_P: U1.AD19(SD1_TX2_P) ; also on sheet 21
MPEX2_RX_N: U1.AG20(SD1_RX3_N) ; also on sheet 21
MPEX2_RX_P: U1.AH20(SD1_RX3_P) ; also on sheet 21
MPEX2_TX_N: U1.AE20(SD1_TX3_N) ; also on sheet 21
MPEX2_TX_P: U1.AD20(SD1_TX3_P) ; also on sheet 21
RS232_CTS1: C276.1 FB21.2 J13.A8 U43.4
RS232_CTS2: C289.1 FB25.2 J13.B8 U43.5
RS232_RTS1: C277.1 FB20.2 J13.A1 U43.2
RS232_RTS2: C290.1 FB24.2 J13.B1 U43.8
RS232_RXD1: C278.1 FB19.2 J13.A6 U43.3
RS232_RXD2: C291.1 FB23.2 J13.B6 U43.6
RS232_TXD1: C279.1 FB18.2 J13.A3 U43.1
RS232_TXD2: C292.1 FB22.2 J13.B3 U43.7
RTC_INT_N: R940.1 U100.7(SQ~{WINT}) ; also on sheet 22
SD_REFCLK1_C_N: C68.2 U1.AA14(SD1_REF_CLK1_N)
SD_REFCLK1_C_P: C67.2 U1.AB14(SD1_REF_CLK1_P)
SD_REFCLK1_N: C68.1 ; also on sheet 24
SD_REFCLK1_P: C67.1 ; also on sheet 24
SD_REFCLK2_C_N: C1381.1 U1.AA18(SD1_REF_CLK2_N)
SD_REFCLK2_C_P: C1380.1 U1.AB18(SD1_REF_CLK2_P)
SD_REFCLK2_N: C1381.2 ; also on sheet 24
SD_REFCLK2_P: C1380.2 ; also on sheet 24
SD_RX1_N: C1268.1 ; also on sheet 21
SD_RX1_P: C1267.1 ; also on sheet 21
SD_TX1_N: U1.AE17(SD1_TX1_N) ; also on sheet 21
SD_TX1_P: U1.AD17(SD1_TX1_P) ; also on sheet 21
SDHC_VS: R882.2 ; also on sheet 9 22
SENSEGND: TP18.1(TP) U1.G20(SENSEGND)
SENSEGNDC: TP16.1(TP) U1.AB10(SENSEGNDC)
SENSEVDD: TP17.1(TP) U1.G19(SENSEVDD) ; also on sheet 25
SENSEVDDC: TP15.1(TP) U1.AB9(SENSEVDDC) ; also on sheet 25
SPI_CLK: R867.2 ; also on sheet 8
SPI_MISO: R868.2 ; also on sheet 8
SPI_MOSI: R869.2 ; also on sheet 8
TDMA_RCK_CLK8_12: J43.21 U1.M4(CLK12)
TDMA_RQ: J43.3 U1.R2(TDMA_RQ)
TDMA_RSYNC: J43.11 U1.U1(TDMA_RSYNC)
TDMA_RXD: J43.13 U1.U2(TDMA_RXD)
TDMA_TCK_CLK9: J43.17 U1.P4(CLK09)
TDMA_TSYNC: J43.9 U1.R1(TDMA_TSYNC)
TDMA_TXD: J43.7 U1.T1(TDMA_TXD)
TDMB_RCK_CLK10: J43.29 U1.P3(CLK10)
TDMB_RQ: J43.24 U1.R4(TDMB_RQ)
TDMB_RSYNC: J43.18 U1.T3(TDMB_RSYNC)
TDMB_RXD: J43.1 U1.U4(TDMB_RXD)
TDMB_TCK_CLK11: J43.39 U1.N4(CLK11)
TDMB_TSYNC: J43.22 U1.R3(TDMB_TSYNC)
TDMB_TXD: J43.20 U1.T4(TDMB_TXD)
TDMR1_INT_N: J43.31 R850.2 ; also on sheet 22
TDMR2_INT_N: J43.33 R851.2 ; also on sheet 22
TDMR_PRS_N: J43.27 R849.2 ; also on sheet 22
TDMR_RST_N: J43.35 R852.2 ; also on sheet 22
TDMR_SLP_N: J43.25 ; also on sheet 22
TDMR_SPI_CS0_N: J43.32 ; also on sheet 8
TDMR_SPI_CS1_N: J43.34 ; also on sheet 8
TEMP_DIODE_N: R206.1 ; also on sheet 9
TEMP_DIODE_P: R205.1 ; also on sheet 9
THERM_ALERT_N: R853.1 U45.6(~{ALERT}/~{THERM2}) ; also on sheet 22
THERM_FAULT_N: R204.1 U45.4(~{THERM}) ; also on sheet 22 28
U_EC2_GTXCLK: C56.1 R128.1 U1.AC8(TSEC_1588_CLK_IN)
U_EC2_TXCTL: R124.1 R126.1 U1.AD8(TSEC_1588_PULSE_OUT2)
U_EC2_TXD0: R117.1 U1.AC7(TSEC_1588_ALARM_OUT2)
U_EC2_TXD1: R118.1 U1.AD7(TSEC_1588_CLK_OUT)
U_EC2_TXD2: R120.1 U1.AB6(TSEC_1588_TRIG_IN1)
U_EC2_TXD3: R122.1 U1.AC6(GPIO3_26)
UART1_CTS_N: U39.9(R2-OUT) ; also on sheet 9
UART1_RTS_N: U39.10(T2-IN) ; also on sheet 9
UART1_RXD: U39.12(R1-OUT) ; also on sheet 9
UART1_TXD: U39.11(T1-IN) ; also on sheet 9
UART2_CTS_N: U41.9(R2-OUT) ; also on sheet 9
UART2_RTS_N: U41.10(T2-IN) ; also on sheet 9
UART2_RXD: U41.12(R1-OUT) ; also on sheet 9
UART2_TXD: U41.11(T1-IN) ; also on sheet 9
USB1_DM: J41.6 L1.3 R168.2 U38.4
USB1_DP: J41.7 L1.2 R167.2 U38.6
USB1_FLG_N: Q3.1(G) R157.2 R159.1 U37.9(~{FLTA})
USB1_PWREN: R162.2 U1.F6(USB1_DRVVBUS) U37.2(ONA)
USB1_VBUS: FB6.1 J41.5
USB1_VBUSCLMP: D4.2 R164.1 R166.2 U1.E4(USB1_VBUSCLMP)
USB2_DM: J41.2 L2.3 R170.2 U38.3
USB2_DP: J41.3 L2.2 R169.2 U38.1
USB2_FLG_N: Q4.1(G) R158.1 R160.2 U37.7(~{FLTB})
USB2_PWREN: R161.2 U1.J5(USB2_DRVVBUS) U37.4(ONB)
USB2_VBUS: FB8.1 J41.1
USB2_VBUSCLMP: D3.2 R163.1 R165.2 U1.J4(USB2_VBUSCLMP)
USB_REFCLK: R880.2 ; also on sheet 9 23
VCORE: C186.1 C187.1 C188.1 C189.1 C200.1 C201.1 C202.1 C203.1 C204.1 C205.1 C206.1 C207.1 C212.1 C213.1 C214.1 C215.1 C216.1 C217.1 C218.1 C219.1 C223.1 C224.1 C225.1 C226.1 C227.1 C228.1 C229.1 C230.1 C904.1 C905.1 C906.1 C907.1 C908.1 C909.1 C910.1 C911.1 C912.1 C913.1 C914.1 C915.1 C1003.1 C1004.1 C1005.1 C1006.1 C1007.1 C1008.1 C1009.1 C1010.1 C1029.1 C1030.1 C1031.1 C1032.1 C1033.1 C1034.1 C1035.1 C1036.1 FB11.2 J11.2 U1.K15(VDD01) U1.K17(VDD02) U1.K19(VDD03) U1.L12(VDD04) U1.L14(VDD05) U1.L16(VDD06) U1.L18(VDD07) U1.L20(NC) U1.M9(NC) U1.M13(VDD08) U1.M15(VDD09) U1.M17(VDD10) U1.M19(NC) U1.N12(VDD11) U1.N14(VDD12) U1.N16(VDD13) U1.N18(VDD14) U1.N20(NC) U1.P9(NC) U1.P11(VDD15) U1.P13(VDD16) U1.P15(VDD17) U1.P17(VDD18) U1.P19(NC) U1.R12(VDD19) U1.R14(VDD20) U1.R16(VDD21) U1.R18(VDD22) U1.R20(NC) U1.T9(NC) U1.T13(VDD23) U1.T15(VDD24) U1.T17(VDD25) U1.T19(NC) U1.U14(VDD26) U1.U16(VDD27) U1.U18(VDD28) U1.U20(NC) U1.V9(NC) U1.V13(VDD29) U1.V15(VDD30) U1.V17(VDD31) U1.V19(NC) U1.W14(NC) U1.Y8(NC) U1.Y9(NC) U1.Y11(NC) ; also on sheet 25
VCORE_SLP: C234.1 C235.1 C236.1 C237.1 C238.1 C239.1 C240.1 C241.1 C916.1 C917.1 C918.1 C919.1 C920.1 C921.1 C922.1 C923.1 C1037.1 C1038.1 C1039.1 U1.K11(VDDC01) U1.K13(VDDC02) U1.L10(VDDC03) U1.M11(VDDC04) U1.N10(VDDC05) U1.R10(VDDC06) U1.T11(VDDC07) U1.U10(VDDC08) U1.U12(VDDC09) U1.V11(VDDC10) U1.W10(VDDC11) U1.W12(VDDC12) ; also on sheet 25
XFI_RX_C_N: C60.2 U1.AG16(SD1_RX0_N)
XFI_RX_C_P: C59.2 U1.AH16(SD1_RX0_P)
XFI_RX_N: C60.1 ; also on sheet 18
XFI_RX_P: C59.1 ; also on sheet 18
XFI_TX_N: U1.AE16(SD1_TX0_N) ; also on sheet 18
XFI_TX_P: U1.AD16(SD1_TX0_P) ; also on sheet 18
XVDD: C249.1 C250.1 C251.1 C252.1 C253.1 C254.1 C255.1 C1014.2 C1026.1 R140.1 U1.AC9(NC) U1.AC12(X1VDD1) U1.AC15(X1VDD2) U1.AC18(X1VDD3) U1.AC21(X1VDD4)
N16869850: C300.2 R211.2 U46.19(RXC)
N16869910: R209.2 U46.14(RXD0/SELRGV)
N16869938: R213.2 U46.16(RXD1/TXDLY)
N16869959: R214.2 U46.17(RXD2/AN0)
N16869976: R215.2 U46.18(RXD3/AN1)
N16869978: R216.2 U46.13(RXCTL/PHY_AD2)
N16870294: R207.1 T1.15
N16870296: C302.1 R207.2 R208.2 R210.2 R212.2
N16870306: R208.1 T1.18
N16870310: R210.1 T1.21
N16870330: R212.1 T1.24
N16870380: C296.2 C298.2 C299.2 C301.2 T1.1 T1.4 T1.7 T1.10
N16870828: C297.1 FB26.2 J14.A11
N16870844: C307.1 FB63.2 J14.A12
N16870888: FB63.1 R219.2
N16870890: C308.1 FB62.2 J14.A9
N16870898: FB62.1 R218.2
N16871038: R221.1 U46.20(~{INT})
N16873302: C304.1 U46.42(CKXTAL1) Y1.1
N16873318: C305.1 U46.43(CKXTAL2) Y1.3
N16873350: R220.2 U46.29(~{PHYRST})
N16874872: C303.1 R217.1 U46.46(CLK125)
N16877780: R222.1 U46.33(~{PME})
N16879465: L3.1 R224.1 U46.48(REG_OUT)
N16880733: R822.2 U46.38(ENSWREG)
N16880820: C309.1 R224.2
N16890207: R227.2 U46.39(RSET)
N16973728: L4.1 R253.1 U49.48(REG_OUT)
N16973810: R825.2 U49.38(ENSWREG)
N16973842: C341.1 R253.2
N16974061: C331.2 R238.2 U49.19(RXC)
N16974094: R239.2 U49.14(RXD0/SELRGV)
N16974110: R242.2 U49.16(RXD1/TXDLY)
N16974123: R243.2 U49.17(RXD2/AN0)
N16974136: R244.2 U49.18(RXD3/AN1)
N16974138: R245.2 U49.13(RXCTL/PHY_AD2)
N16974225: R236.1 T2.15
N16974227: C334.1 R236.2 R237.2 R240.2 R241.2
N16974244: R237.1 T2.18
N16974248: R240.1 T2.21
N16974260: R241.1 T2.24
N16974322: C328.2 C330.2 C332.2 C333.2 T2.1 T2.4 T2.7 T2.10
N16974528: C329.1 FB29.2 J14.B11
N16974538: C337.1 FB61.2 J14.B12
N16974570: FB61.1 R248.2
N16974572: C338.1 FB60.2 J14.B9
N16974576: FB60.1 R247.2
N16974631: R250.1 U49.20(~{INT})
N16974829: C339.1 U49.42(CKXTAL1) Y2.1
N16974847: C340.1 U49.43(CKXTAL2) Y2.3
N16974885: R249.2 U49.29(~{PHYRST})
N16975047: C335.1 R246.1 U49.46(CLK125)
N16975158: R251.1 U49.33(~{PME})
N16975193: R256.2 U49.39(RSET)
N17013042: L1.1 R167.1 U1.F1(USB1_UDP)
N17013078: L1.4 R168.1 U1.F2(USB1_UDM)
N17013302: R172.2 U1.H4(USB2_UID)
N17013307: R173.2 U1.F4(USB1_UID)
N17013374: C1022.1 R171.2 U1.G4(USB_IBIAS_REXT)
N17020476: L2.1 R169.1 U1.H1(USB2_UDP)
N17020482: L2.4 R170.1 U1.H2(USB2_UDM)
N17021052: FB9.1 J41.4
N17021059: FB7.1 J41.8
N17021121: Q3.3(D) R156.1 R157.1 U1.F5(USB1_PWRFAULT)
N17021131: Q4.3(D) R155.1 R160.1 U1.H5(USB2_PWRFAULT)
N17055310: C273.1 U39.2(V+)
N17055339: C275.1 U39.6(V-)
N17055373: C271.2 U39.1(C1+)
N17055376: C271.1 U39.3(C1-)
N17055394: C274.2 U39.4(C2+)
N17055396: C274.1 U39.5(C2-)
N17055419: R196.1 U39.14(T1-OUT)
N17055422: R197.1 U39.13(R1-IN)
N17055459: R199.1 U39.8(R2-IN)
N17055461: R198.1 U39.7(T2-OUT)
N17055495: FB18.1 R196.2
N17055507: FB19.1 R197.2
N17055527: FB20.1 R198.2
N17055529: FB21.1 R199.2
N17056698: C287.1 U41.2(V+)
N17056714: C288.1 U41.6(V-)
N17056740: C285.2 U41.1(C1+)
N17056750: C285.1 U41.3(C1-)
N17056764: C284.2 U41.4(C2+)
N17056766: C284.1 U41.5(C2-)
N17056776: R200.1 U41.14(T1-OUT)
N17056778: R201.1 U41.13(R1-IN)
N17056796: R203.1 U41.8(R2-IN)
N17056798: R202.1 U41.7(T2-OUT)
N17056816: FB22.1 R200.2
N17056834: FB23.1 R201.2
N17056844: FB24.1 R202.2
N17056846: FB25.1 R203.2
N17059643: R130.1 U1.U6(EMI2_MDC)
N17059732: R121.2 U1.AC3(EC1_TXD3)
N17059733: R116.2 U1.AE4(EC1_TXD1)
N17059734: R119.2 U1.AD3(EC1_TXD2)
N17059735: R115.2 U1.AE3(EC1_TXD0)
N17059985: R123.2 R125.2 U1.AF4(EC1_TX_EN)
N17060054: C55.2 R127.2 U1.AF3(EC1_GTX_CLK)
N17060498: R129.2 U1.AH3(EMI1_MDC)
N17082319: R140.2 U1.Y20(SD1_IMP_CAL_TX)
N17082346: R139.2 U1.AA12(SD1_IMP_CAL_RX)
N18287015: R138.1 U23.4(C) U24.4(C)
N18586245: C294.2 R205.2 U45.2(D+)
N18586247: C294.1 R206.2 U45.3(D-)
N20562248: TP11.1(TP) U1.Y15(SD1_PLL1_TPA)
N20562257: TP12.1(TP) U1.AB15(SD1_PLL1_TPD)
N20562271: TP13.1(TP) U1.Y19(SD1_PLL2_TPA)
N20562273: TP14.1(TP) U1.AB19(SD1_PLL2_TPD)
N20562350: C1022.2 R814.2
N21754633: J43.28 R867.1
N21754692: J43.36 R868.1
N21754708: J43.38 R869.1
N23085337: C1116.1 J49.1 R883.1
N23085351: R883.2 U100.3(VBACKUP)
N23085389: U100.2(X2) Y6.1
N23085395: U100.1(X1) Y6.4
N23178619: R875.2 U1.AB1(NC)
N23180170: R881.2 U1.AD5(NC)
N23371818: R876.1 R882.1 U1.D1(NC)
N23371833: R877.1 U1.D4(NC)
N23371894: R878.1 U1.D5(NC)
N23373428: R879.1 U1.E9(NC)
N23374222: R880.1 U1.F8(NC)
N23535138: R951.2 U37.3(ISET)
N23965067: C1268.2 U1.AG17(SD1_RX1_N)
N23965070: C1267.2 U1.AH17(SD1_RX1_P)

Not connected (* = marked no-connect by the designer): J13 A2* A7* B2* B7*; J43 8*; U1 AA5(NC)* AA6(NC)* AA8(NC)* AA9(NC)* AA10(NC)* AB8(NC)* AB11(NC)* AB12(NC)* AC4(NC)* AD10(NC)* AD11(NC)* AD13(NC)* AD14(NC)* AE7(NC)* AE10(NC)* AE11(NC)* AE13(NC)* AE14(NC)* AF6(NC)* AF7(NC)* AG5(NC)* AG7(NC)* AG8(NC)* AG28(NC_DET)* AH5(NC)* AH8(NC)* AH27(NC)* C17(NC)* C19(NC)* D18(NC)* E17(NC)* F10(TH_TPA)* F21(NC)* G6(NC)* G17(NC)* H6(NC)* H21(NC)* J6(NC)* K22(NC)* L6(NC)* M6(NC)* M22(NC)* N6(NC)* P5(NC)* P6(NC)* P22(NC)* R5(NC)* R6(NC)* U5(NC)* U22(NC)* V2(NC)* V5(NC)* V21(NC)* W3(NC)* W6(NC)* W21(NC)* Y5(NC)* Y6(NC)* Y21(NC)*; U46 12(NC)*; U47 5*; U48 5*; U49 12(NC)*; U50 5*; U51 5*

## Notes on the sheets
sheet 10
- T1024 ETHERNET and SERDES INTERFACE
- EC1&EC2 OPERATE AT 2.5V EXCEPT EMI2 OPERATES AT 1.2V
sheet 11
- T1024 QE INTERFACE
- TDM RISER CARD CONNECTOR
- T1024 DVDD: 3.3V
sheet 12
- T1024 USB INTERFACE
- USB1&2 FOR HOST MODE
sheet 13
- T1024 POWER SUPPLY
- USB_SVDD supply must ramp before or after the
  USB_HVDD and USB_OVDD supplies have ramped.
- Though hole test points, route as differential signals
- LABEL = PROG_SFP
- LABEL = PROG_MTR
- LABEL = FA_VDD
sheet 14
- T1024 PLL FILTERs and GROUND
- Compatible with T1040
- SD1_RX3_P
- SD1_RX2_P
- IRQ8_B
- IFC_CS5_B
- IFC_CS7_B
- IRQ3_B
- IRQ4_B
- EC1_COL
- IRQ5_B
- EC1_RXER
- IFC_CS6_B
- X1VDD
- IFC_CS4_B
- IRQ2_B
- USB_REFCLK
- IRQ7_B
- AVDD_CG2
- VDD
- VDD
- VDD
- VDD
- VDD
- VDD
- VDD
- VDD
- VDD
- SD1_RX0_N
- VDD
- SD1_RX1_N
- Compatible with T1040
- SD1_RX2_N
- SD1_RX3_N
- VDD
- SD1_RX0_P
- SD1_RX1_P
- VDD
- VDD
- VDD
- VDD
- VDD
sheet 15
- T1024 DUART and I2C DEVICE INTERFACE
- RTC
- I2C EEPROM
- I2C ADR = 0x68
- I2C ADDR = 0x50
- For RS232 ESD protection, place close to RJ45 connector
- I2C THERMAL MONITOR
- I2C ADDR = 0x4C
sheet 16
- RGMII ETHERNET PORT 1
- 100 ohms
  DIFF PAIRs
- For Gigabit Ethernet protection, place close to magnetics
- RGMII PHY POWER-ON STRAPPINGs
- SELRGV
- TXDLY
- 2.5V
- AN0
- NWay, advertize all capability
- AN1
- PHY_AD2
- PHY_AD0
- PHY ADDR = 0x02
- PHY_AD1
- RXDLY
sheet 17
- RGMII ETHERNET PORT 2
- 100 ohms
  DIFF PAIRs
- For Gigabit Ethernet protection, place close to magnetics
- RGMII PHY POWER-ON STRAPPINGs
- SELRGV
- TXDLY
- 2.5V
- AN0
- NWay, advertize all capability
- AN1
- PHY_AD2
- PHY_AD0
- PHY ADDR = 0x06
- PHY_AD1
- RXDLY
